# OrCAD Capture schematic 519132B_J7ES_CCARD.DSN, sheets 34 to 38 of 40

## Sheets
34 38.DEBUG: size C; rev: A
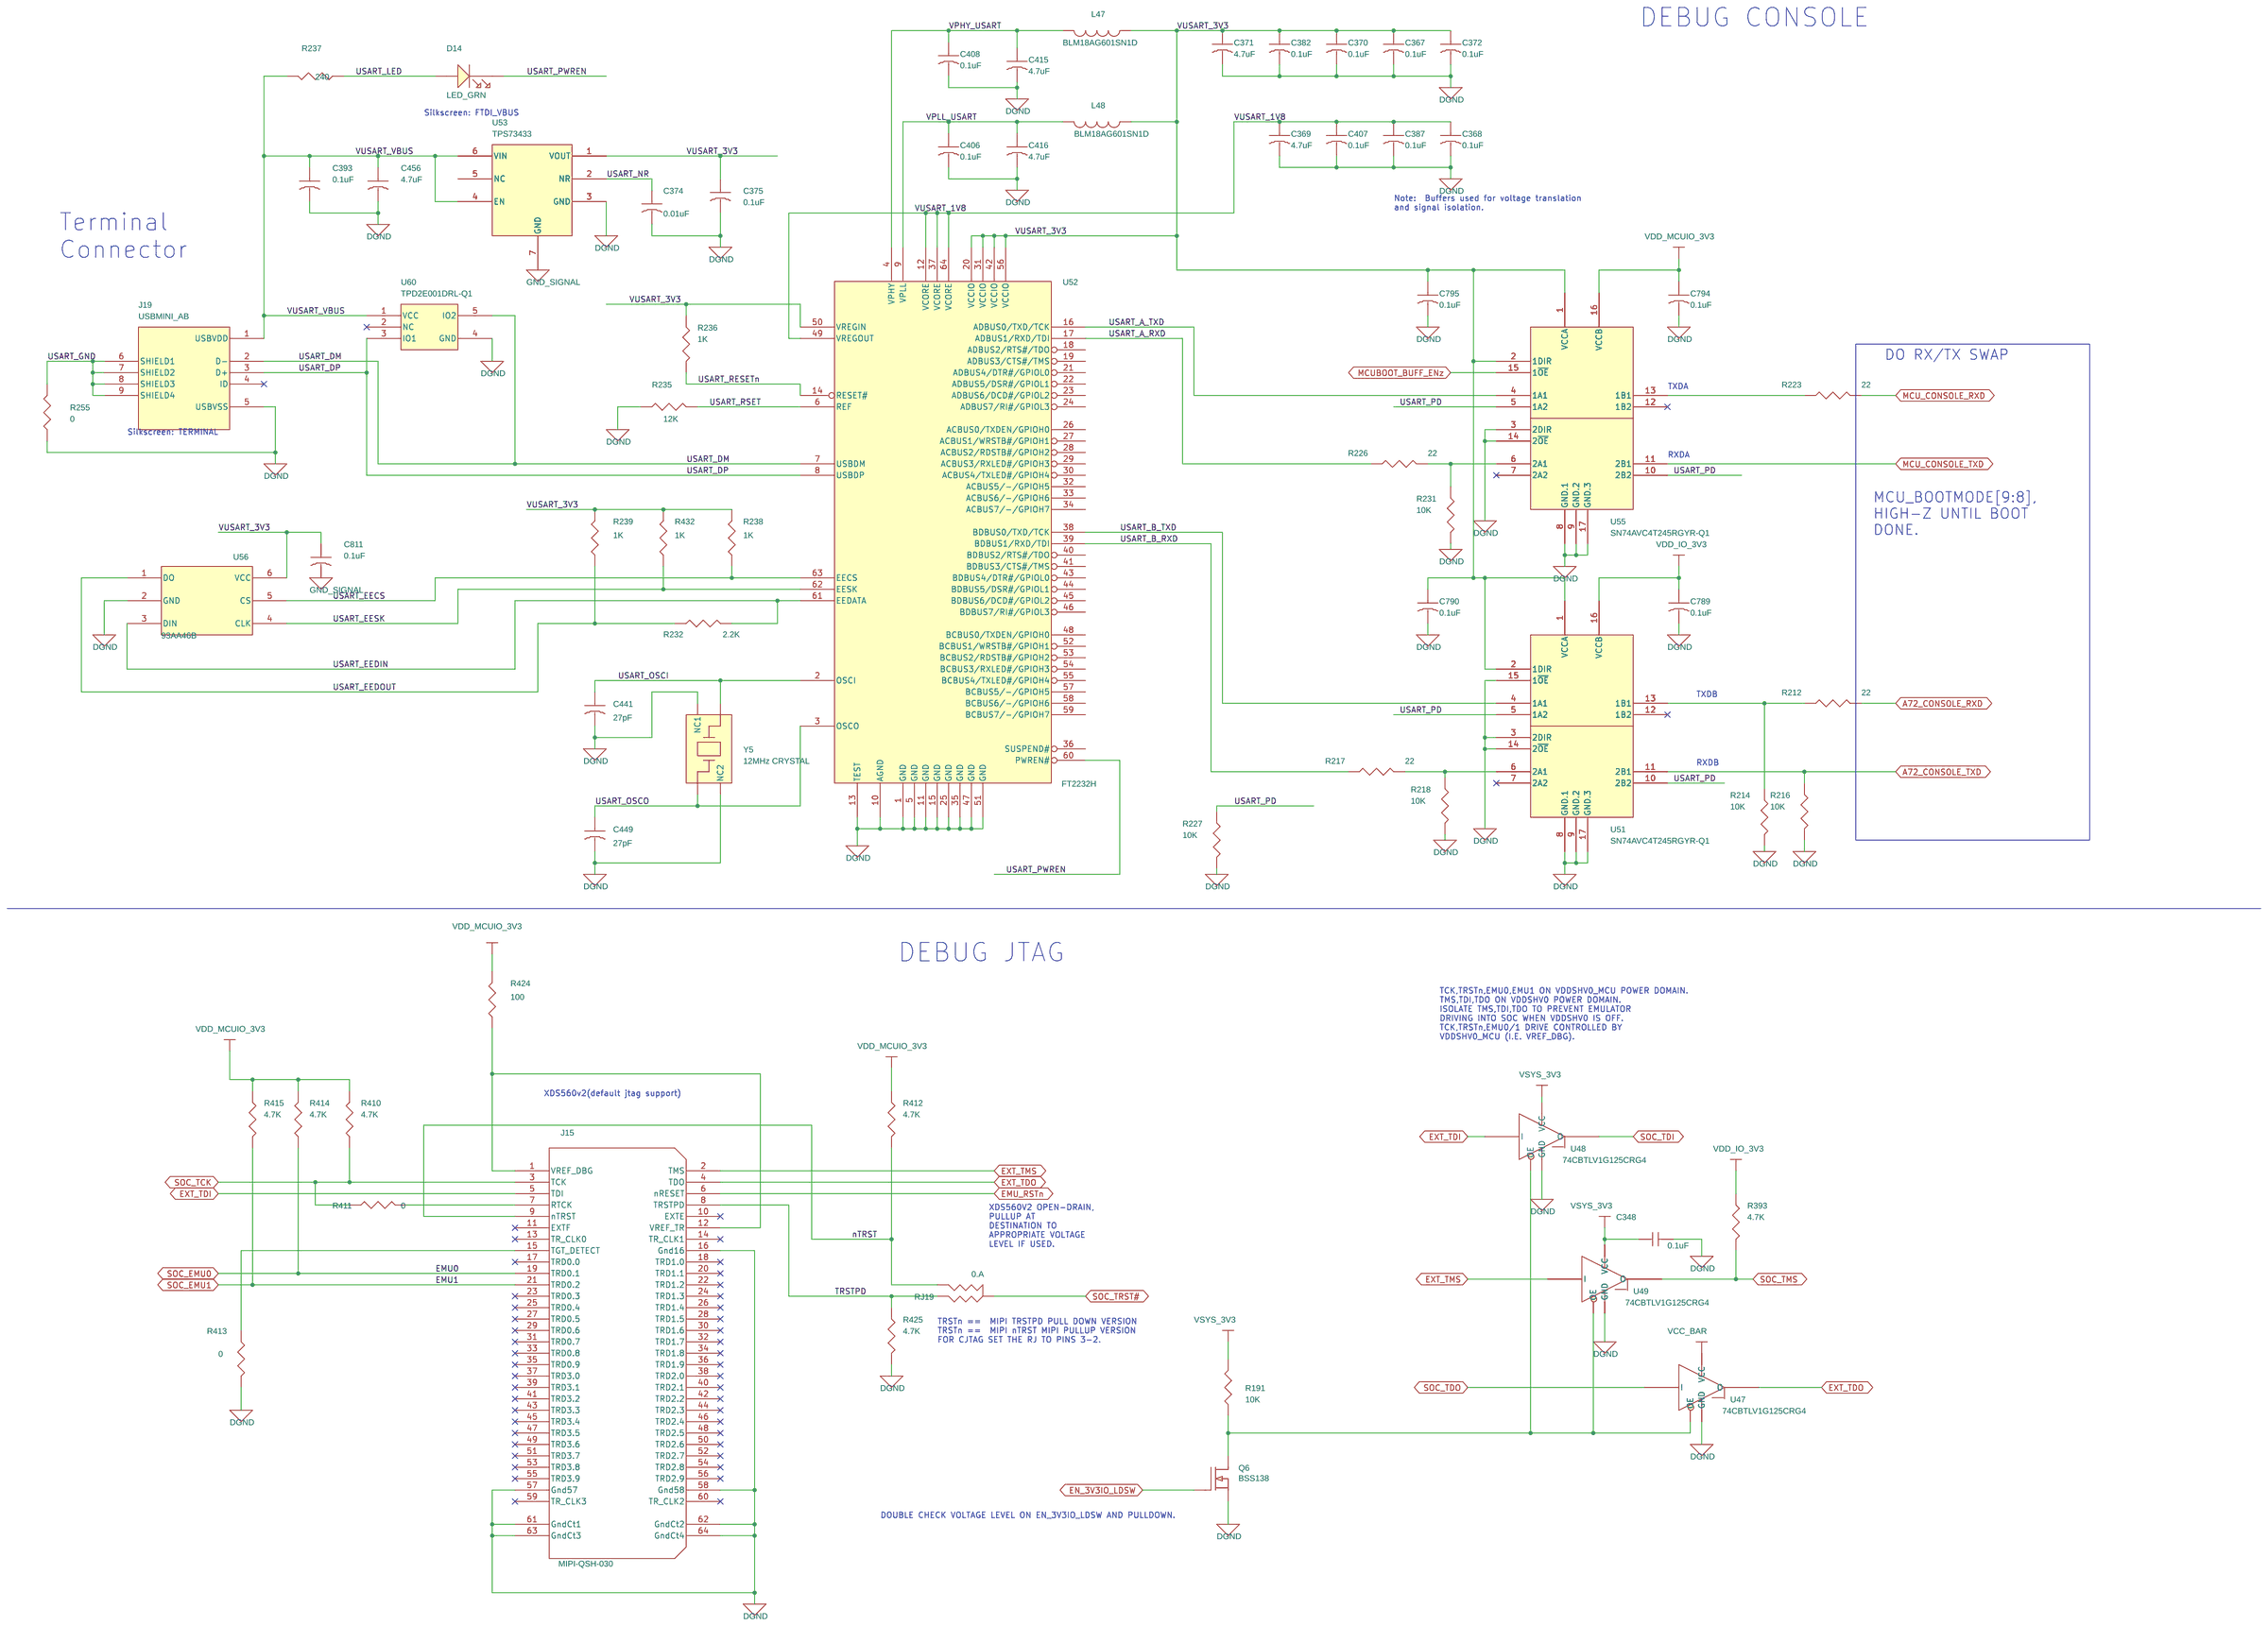
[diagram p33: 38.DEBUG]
35 39.TUNER: size C; rev: A
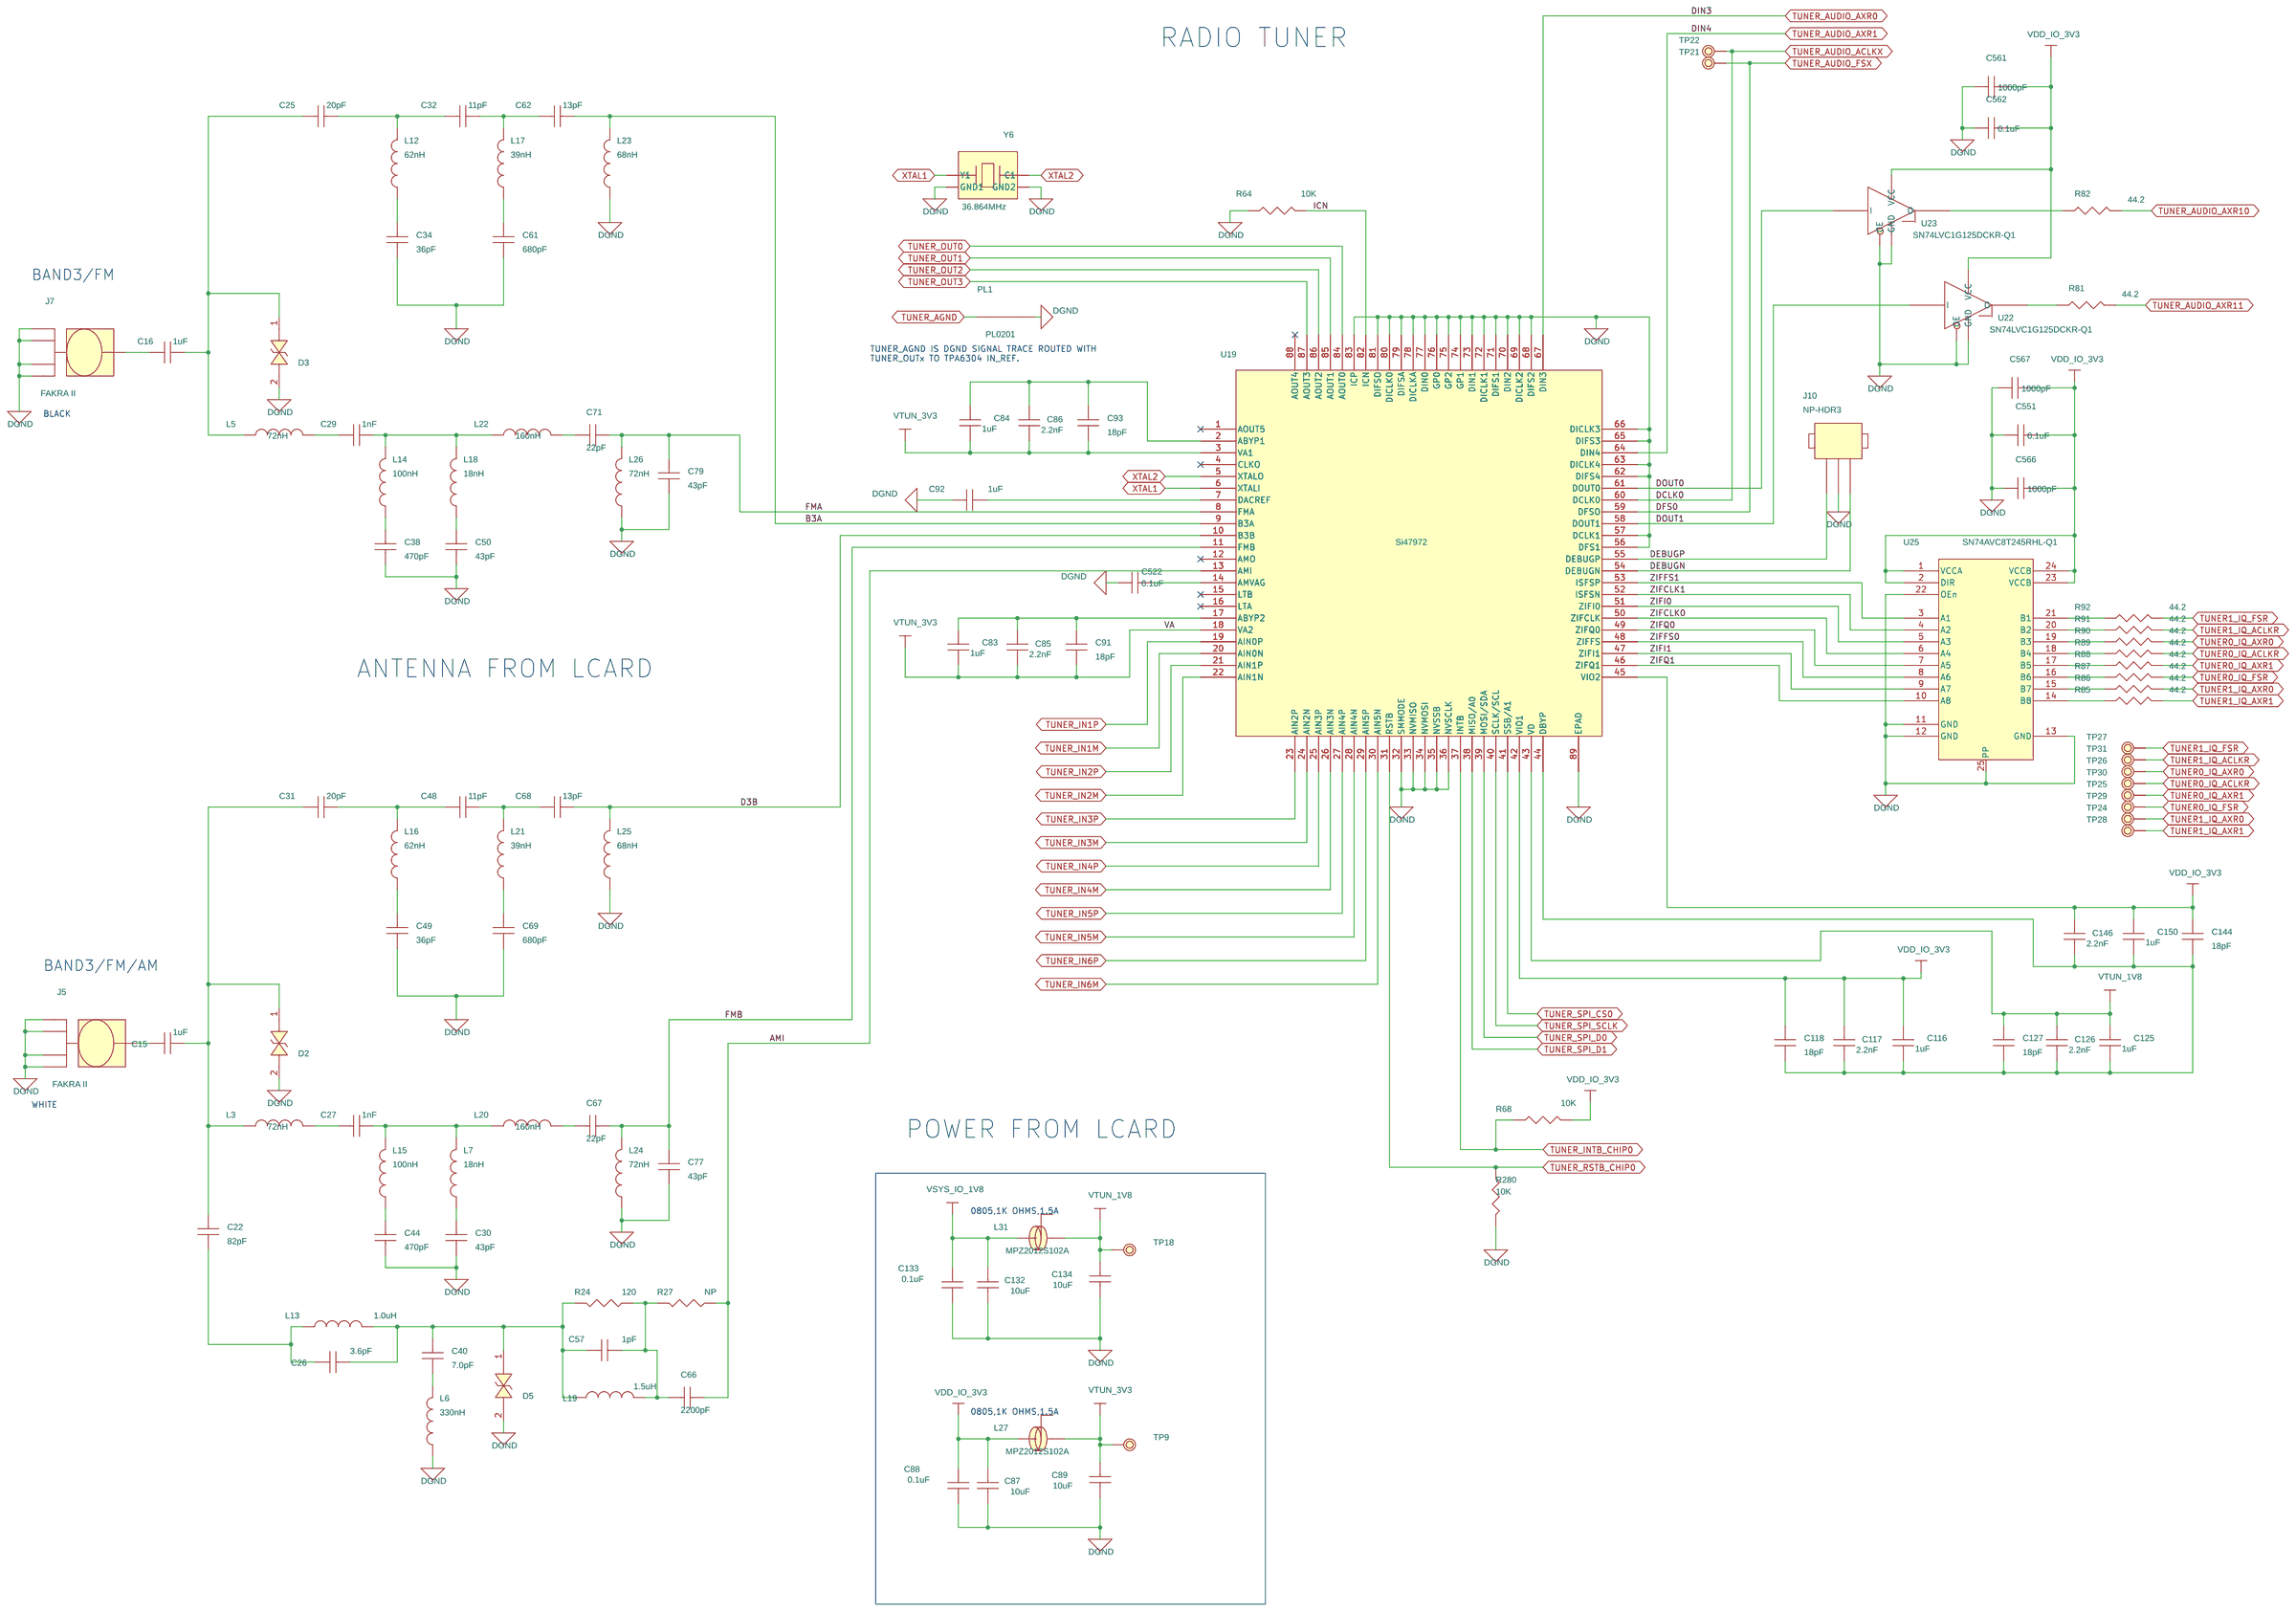
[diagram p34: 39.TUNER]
36 40. DEBUG SDCARD: size C; rev: A
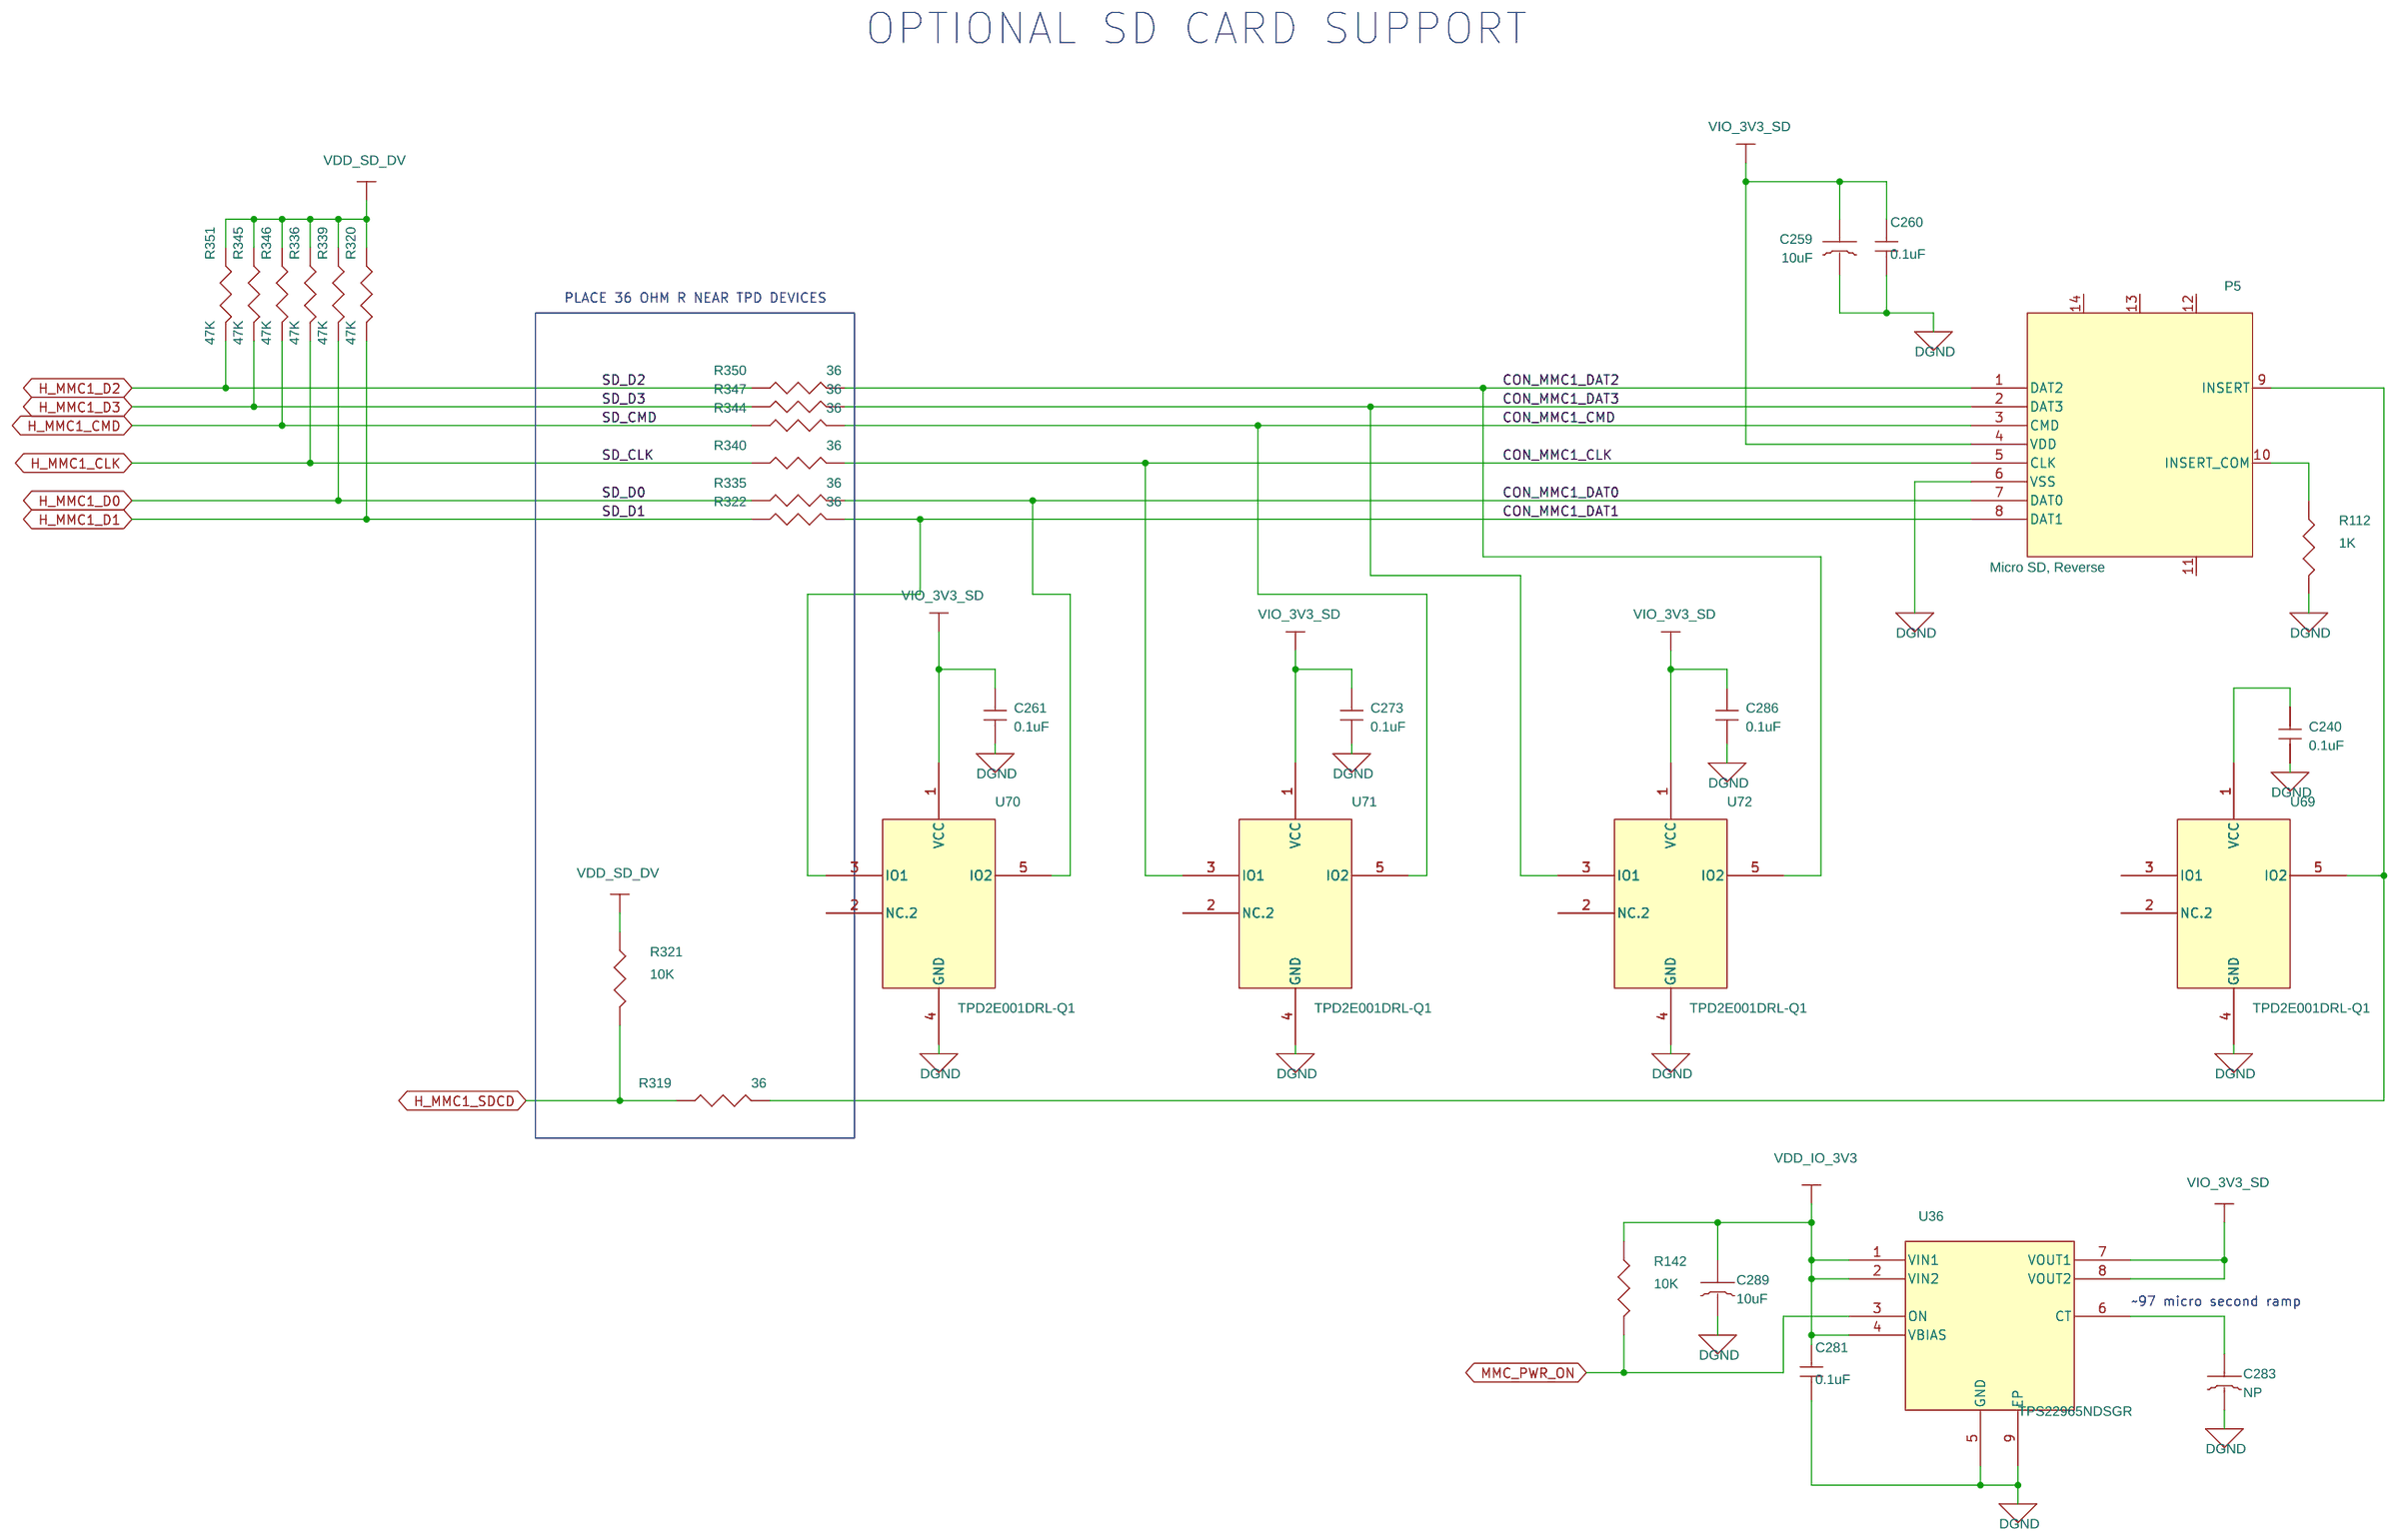
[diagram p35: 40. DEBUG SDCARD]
37 32.ENET/CAN: size C; rev: B
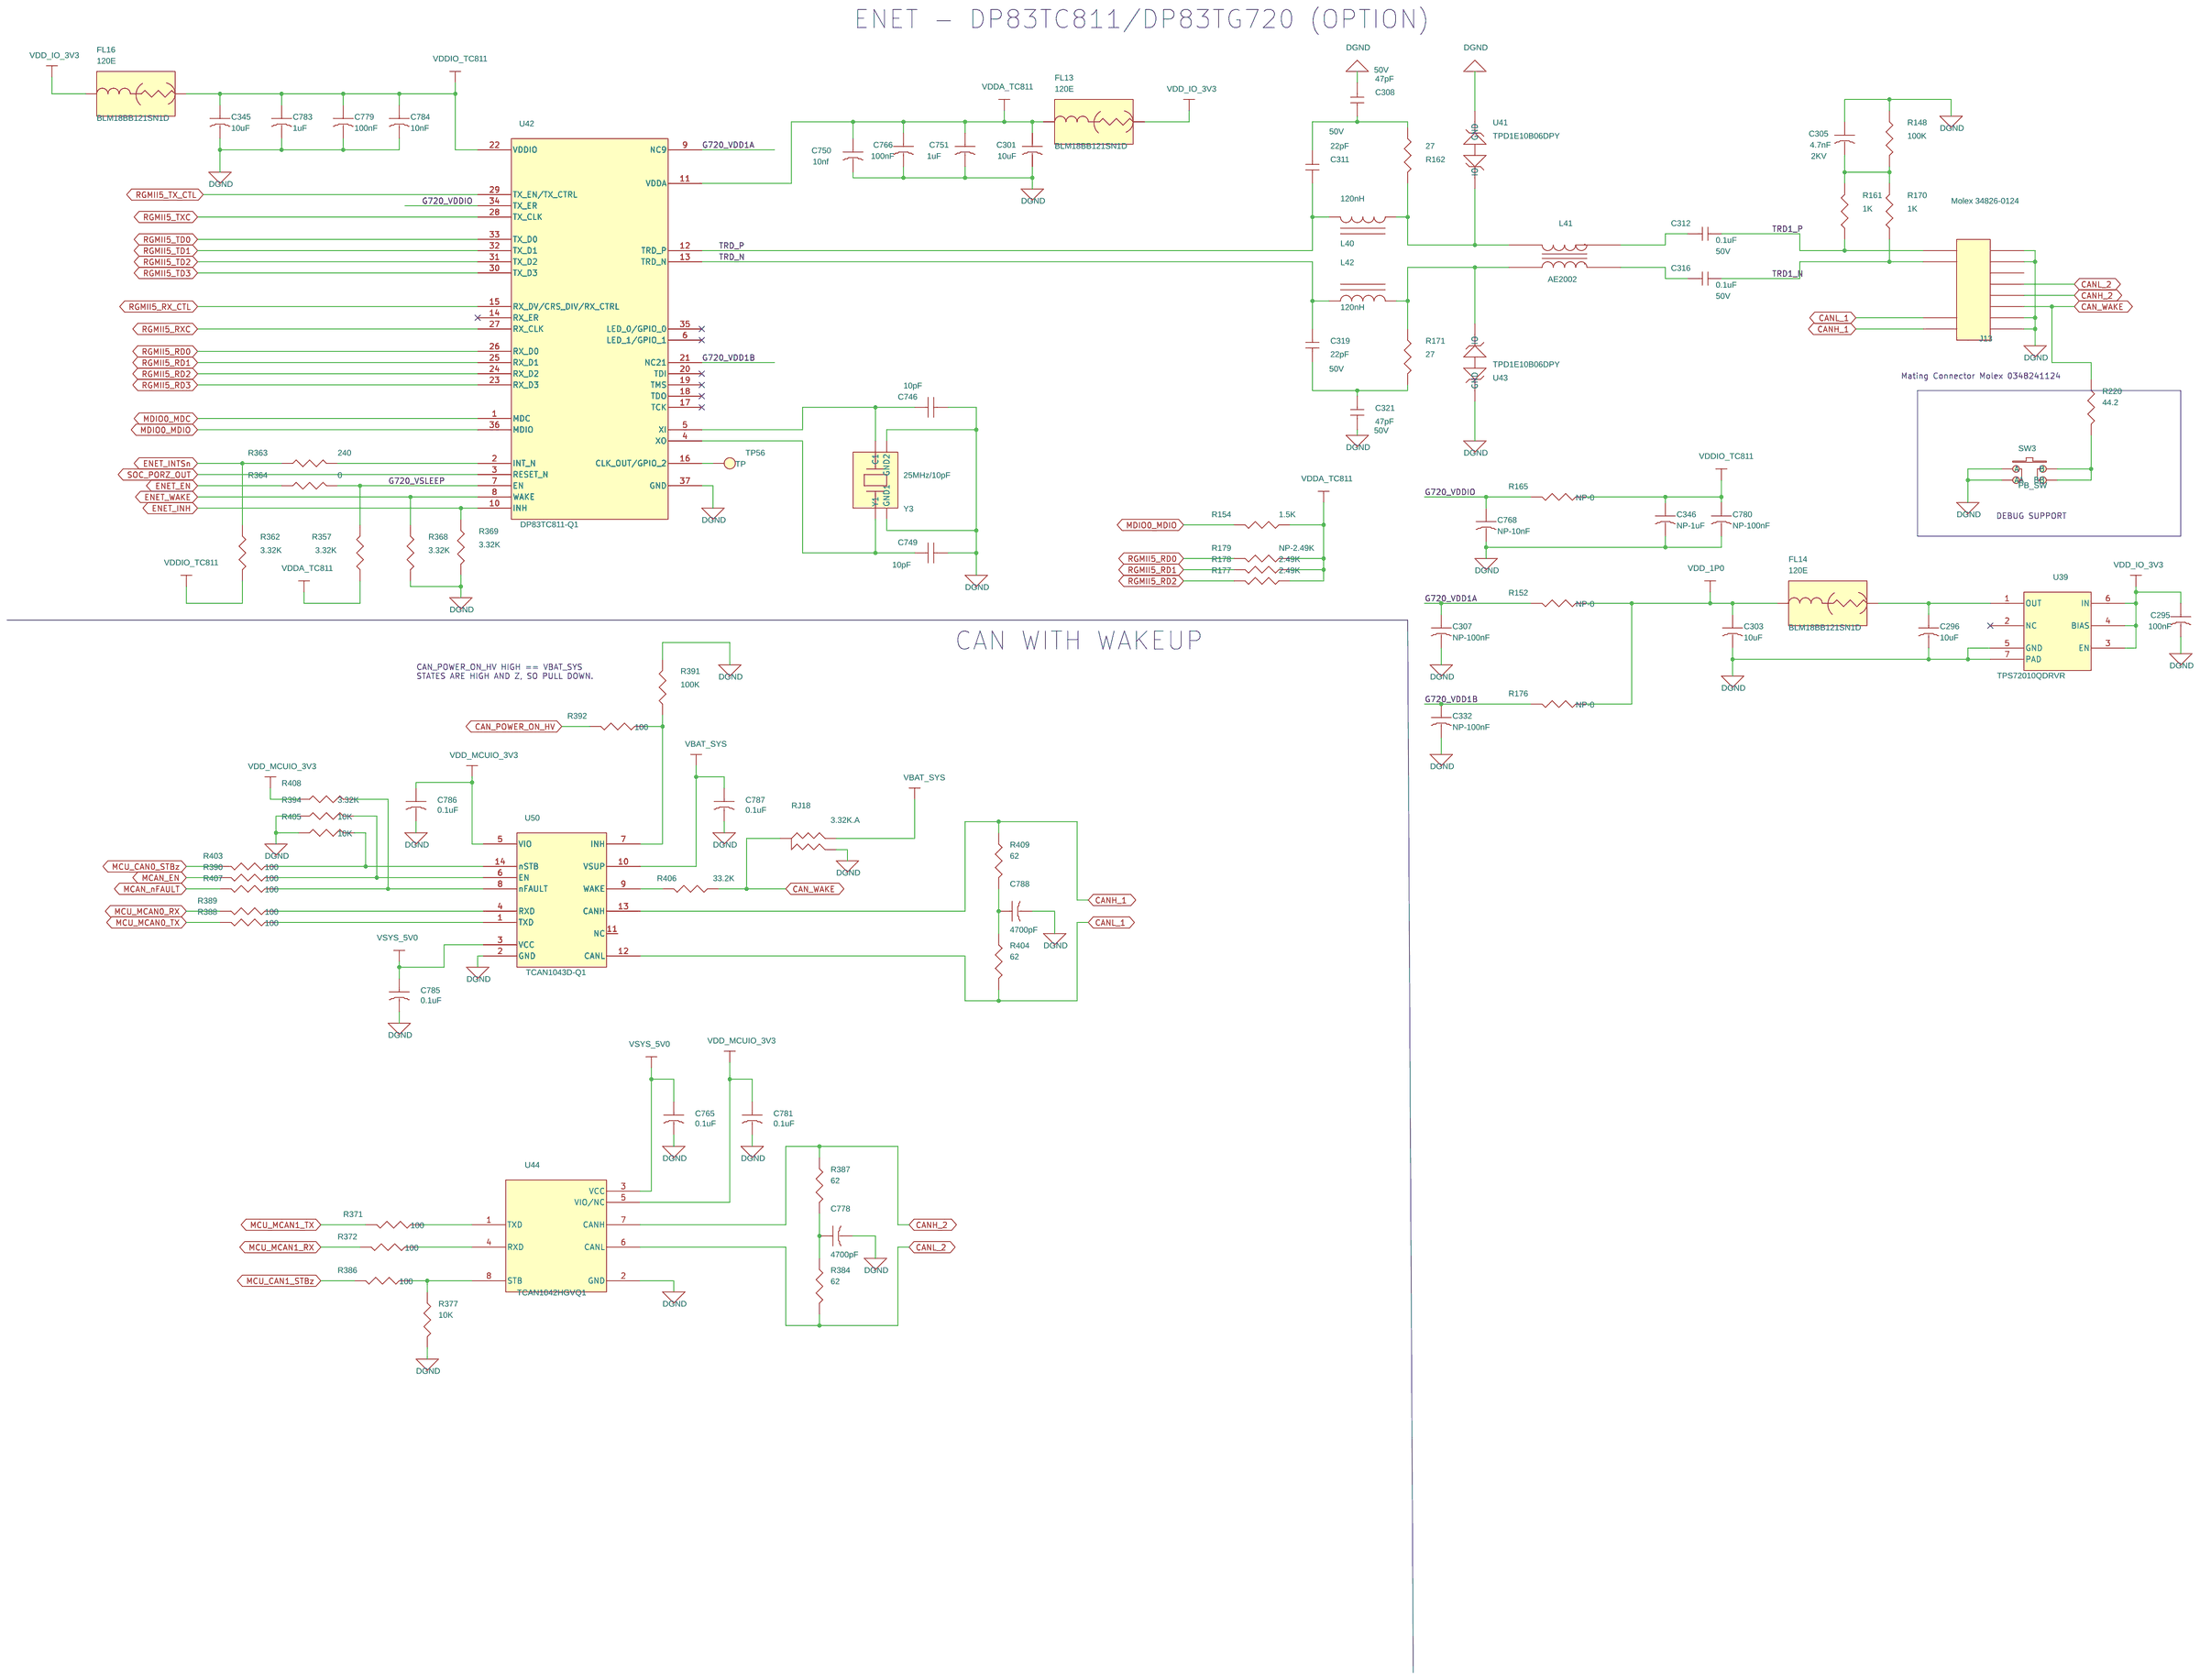
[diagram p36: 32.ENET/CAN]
38 34. USB HUB/WIFI: size C; rev: A
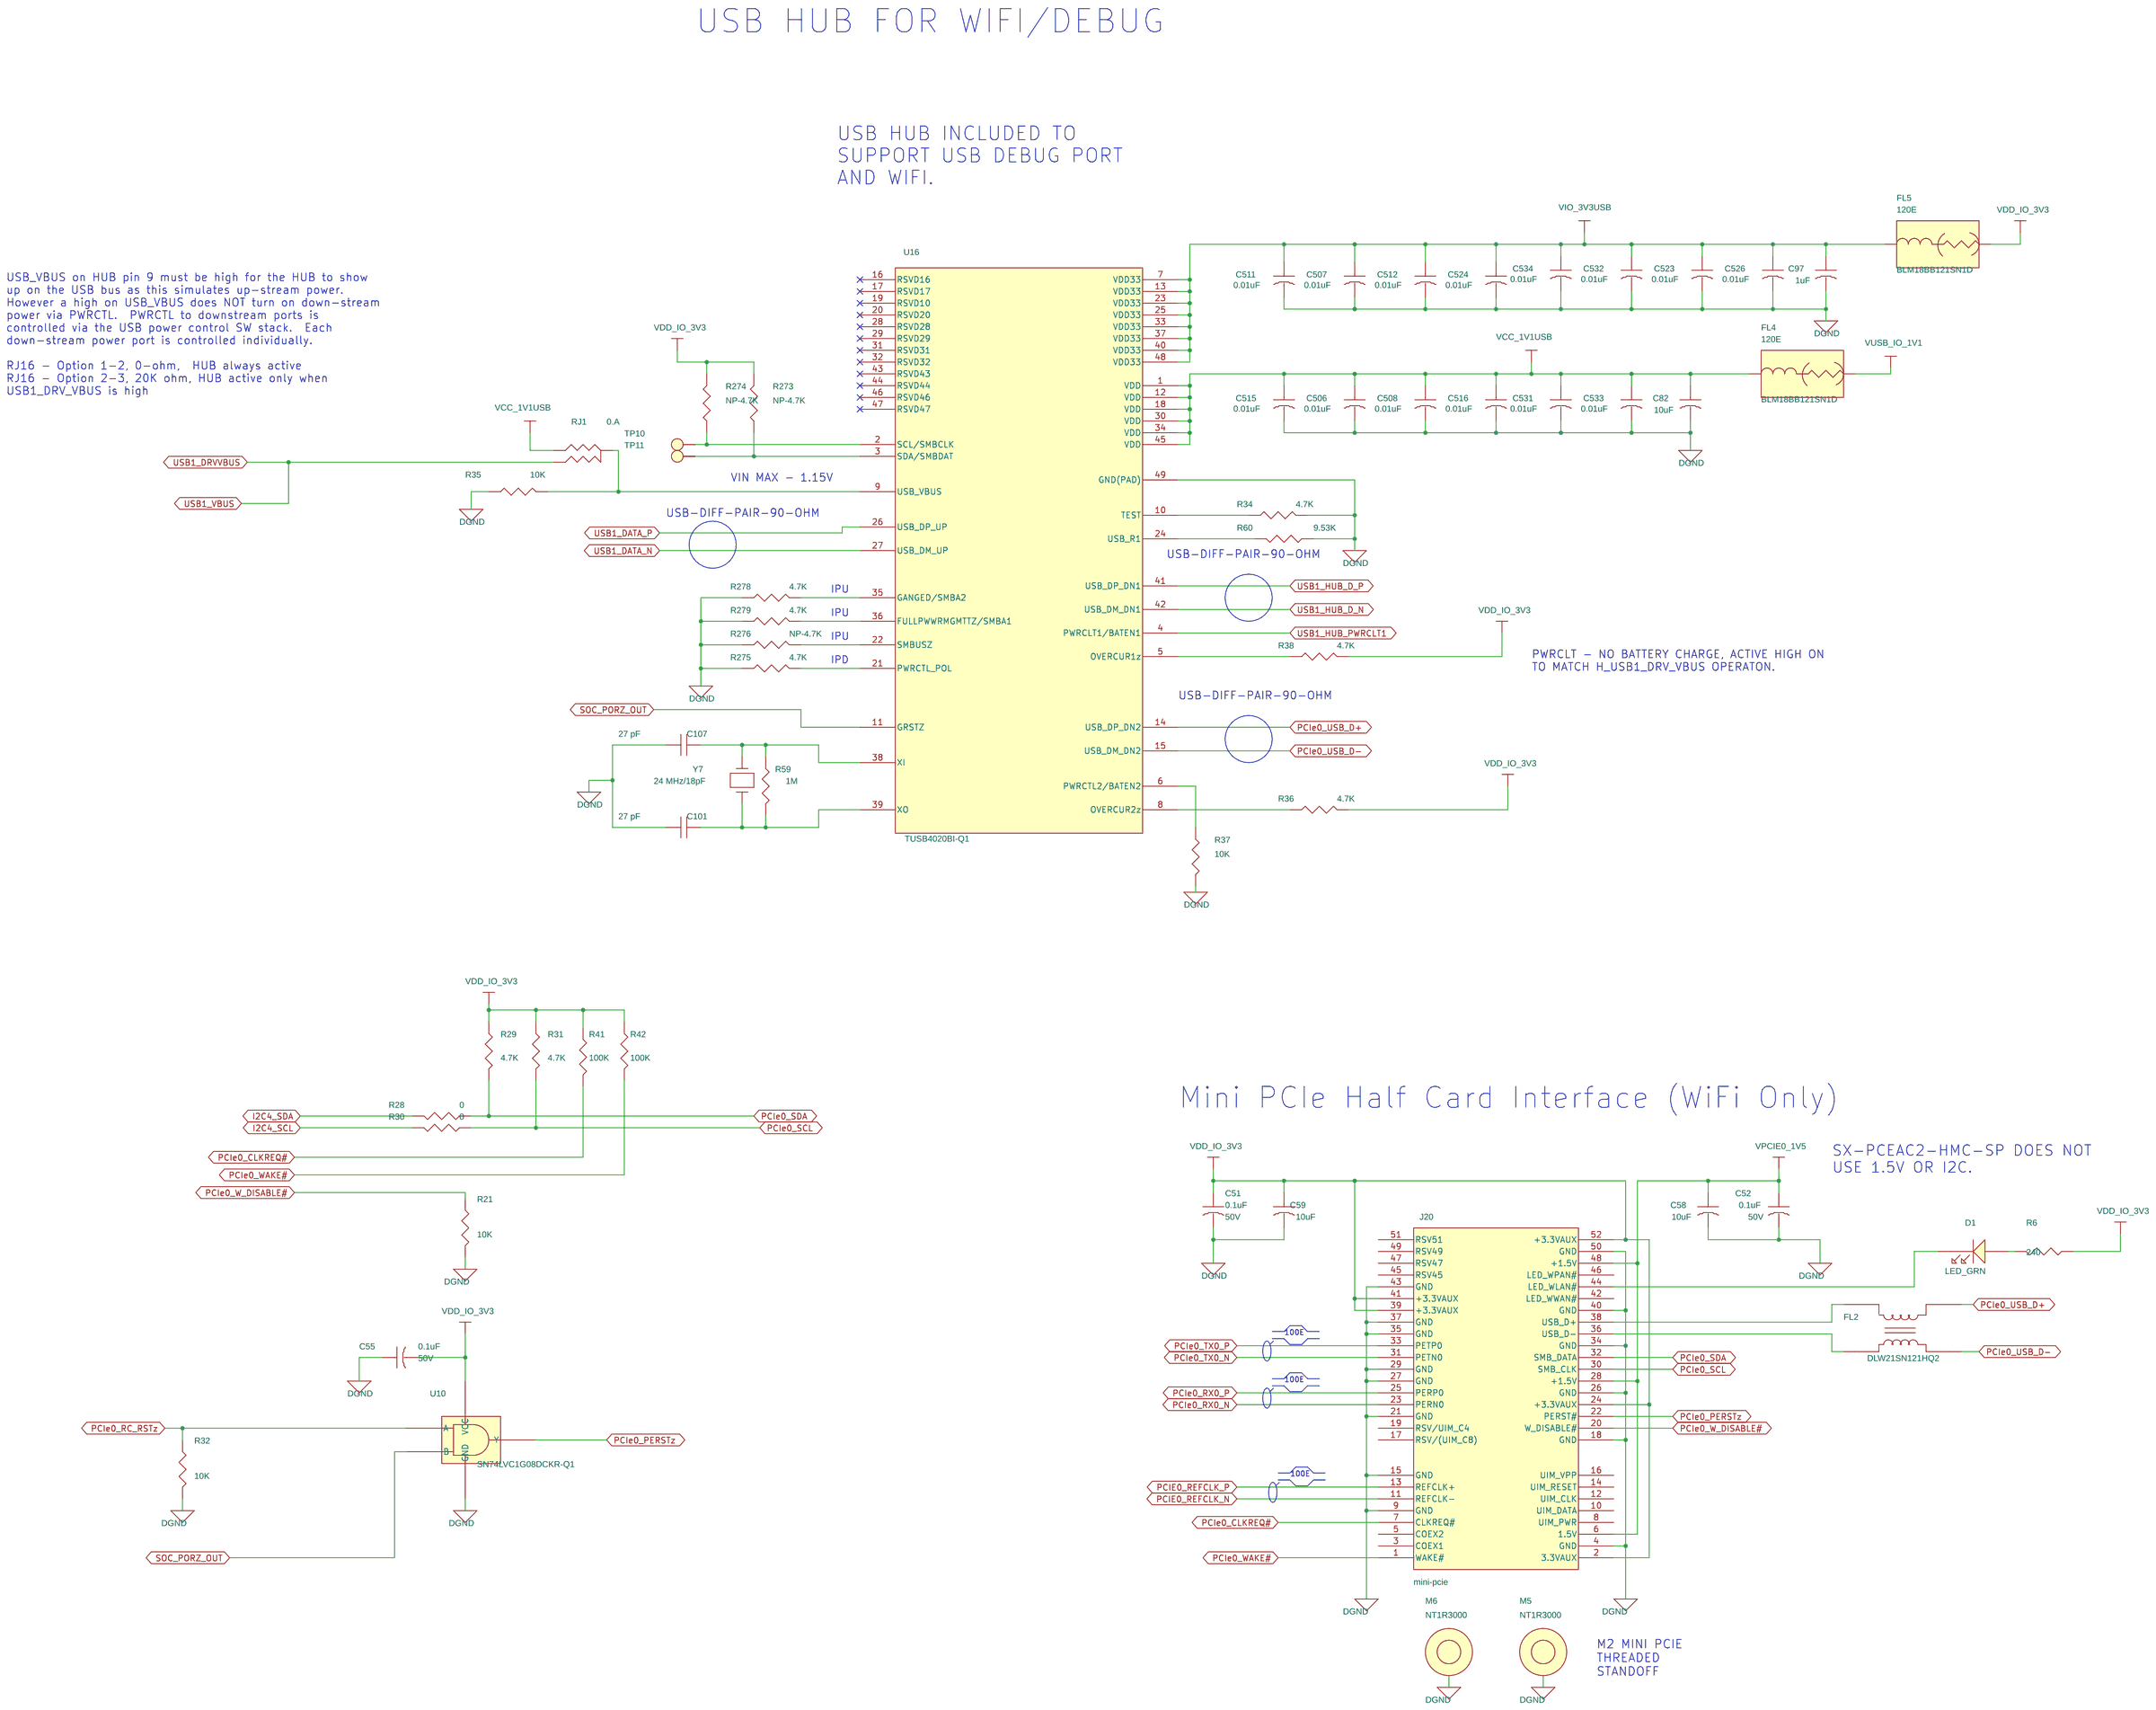
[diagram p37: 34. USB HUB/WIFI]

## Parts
sheet 32.ENET/CAN
C295  100nF  [c402-25]
C296  10uF  [c805-35x60]
C301  10uF  [c805-35x60]
C303  10uF  [c805-35x60]
C305  4.7nF  [c1210-70x102]
C307  NP-100nF  [c402-25]
C308  47pF  [c402-25]
C311  22pF  [c603-35x45]
C312  0.1uF  [c603-35x45]
C316  0.1uF  [c603-35x45]
C319  22pF  [c603-35x45]
C321  47pF  [c402-25]
C332  NP-100nF  [c402-25]
C345  10uF  [c805-35x60]
C346  NP-1uF  [c402-25]
C746  10pF  [c402-25]
C749  10pF  [c402-25]
C750  10nf  [c402-25]
C751  1uF  [c402-25]
C765  0.1uF  [c402-25]
C766  100nF  [c402-25]
C768  NP-10nF  [c402-25]
C778  4700pF  [c402-25]
C779  100nF  [c402-25]
C780  NP-100nF  [c402-25]
C781  0.1uF  [c402-25]
C783  1uF  [c402-25]
C784  10nF  [c402-25]
C785  0.1uF  [c402-25]
C786  0.1uF  [c402-25]
C787  0.1uF  [c402-25]
C788  4700pF  [c402-25rd]
FL13  120E  [EMIFIL_BLM18A_0603]
FL14  120E  [EMIFIL_BLM18A_0603]
FL16  120E  [EMIFIL_BLM18A_0603]
J13  Molex 34826-0124  [molex-34826-0124]
L40  120nH  [ind1608-27x40]
L41  AE2002  [choke4-ae2002]
L42  120nH  [ind1608-27x40]
R148  100K  [r402-25]
R152  NP-0  [r402-25]
R154  1.5K  [r402-25]
R161  1K  [r402-25]
R162  27  [r402-25]
R165  NP-0  [r402-25]
R170  1K  [r402-25]
R171  27  [r402-25]
R176  NP-0  [r402-25]
R177  2.49K  [r402-25]
R178  2.49K  [r402-25]
R179  NP-2.49K  [r402-25]
R220  44.2  [r201-18p5x15]
R357  3.32K  [r402-25]
R362  3.32K  [r402-25]
R363  240  [r402-25]
R364  0  [r402-25]
R368  3.32K  [r402-25]
R369  3.32K  [r402-25]
R371  100  [r402-25]
R372  100  [r402-25]
R377  10K  [r402-25]
R384  62  [r1206-40x70]
R386  100  [r402-25]
R387  62  [r1206-40x70]
R388  100  [r402-25]
R389  100  [r402-25]
R390  100  [r402-25]
R391  100K  [r402-25]
R392  100  [r402-25]
R394  10K  [r402-25]
R403  100  [r402-25]
R404  62  [r1206-40x70]
R405  10K  [r402-25]
R406  33.2K  [r402-25]
R407  100  [r402-25]
R408  3.32K  [r402-25]
R409  62  [r1206-40x70]
RJ18  3.32K.A  [JMP402-25]
SW3  PB_SW  [SW4-7914G]
TP56  TP  [tp-30RD13]
U39  TPS72010QDRVR  [drv6-12x30]
U41  TPD1E10B06DPY  [dpy]
U42  DP83TC811-Q1  [rnd36-24x10]
U43  TPD1E10B06DPY  [dpy]
U44  TCAN1042HGVQ1  [so8-25x75]
U50  TCAN1043D-Q1  [so14-25x75]
Y3  25MHz/10pF  [xtal4-abm11]
sheet 34. USB HUB/WIFI
C51  0.1uF  [c402-25]
C52  0.1uF  [c402-25]
C55  0.1uF  [c402-25]
C58  10uF  [c805-35x60]
C59  10uF  [c805-35x60]
C82  10uF  [c603-35x45]
C97  1uF  [c603-35x45]
C101  27 pF  [C402-25]
C107  27 pF  [C402-25]
C506  0.01uF  [c402-25]
C507  0.01uF  [c402-25]
C508  0.01uF  [c402-25]
C511  0.01uF  [c402-25]
C512  0.01uF  [c402-25]
C515  0.01uF  [c402-25]
C516  0.01uF  [c402-25]
C523  0.01uF  [c402-25]
C524  0.01uF  [c402-25]
C526  0.01uF  [c402-25]
C531  0.01uF  [c402-25]
C532  0.01uF  [c402-25]
C533  0.01uF  [c402-25]
C534  0.01uF  [c402-25]
D1  LED_GRN  [led1206-59x59]
FL2  DLW21SN121HQ2  [EMI-36X15-DLW21]
FL4  120E  [EMIFIL_BLM18A_0603]
FL5  120E  [EMIFIL_BLM18A_0603]
J20  mini-pcie  [molex-67910-0002]
M5  NT1R3000  [mhp098-175pip]
M6  NT1R3000  [mhp098-175pip]
R6  240  [r402-25]
R21  10K  [r402-25]
R28  0  [r402-25]
R29  4.7K  [r402-25]
R30  0  [r402-25]
R31  4.7K  [r402-25]
R32  10K  [r402-25]
R34  4.7K  [r402-25]
R35  10K  [r402-25]
R36  4.7K  [r402-25]
R37  10K  [r402-25]
R38  4.7K  [r402-25]
R41  100K  [r402-25]
R42  100K  [r402-25]
R59  1M  [r402-25]
R60  9.53K  [r402-25]
R273  NP-4.7K  [r402-25]
R274  NP-4.7K  [r402-25]
R275  4.7K  [r402-25]
R276  NP-4.7K  [r402-25]
R278  4.7K  [r402-25]
R279  4.7K  [r402-25]
RJ1  0.A  [JMP402-25]
TP10  TP  [tp-30RD13]
TP11  TP  [tp-30RD13]
U10  SN74LVC1G08DCKR-Q1  [dck-5]
U16  TUSB4020BI-Q1  [php48-12x70]
Y7  24 MHz/18pF  [xtal2-75x94]
sheet 38.DEBUG
C348  0.1uF  [c402-25]
C367  0.1uF  [c402-25]
C368  0.1uF  [c402-25]
C369  4.7uF  [C805-35X60]
C370  0.1uF  [c402-25]
C371  4.7uF  [C805-35X60]
C372  0.1uF  [c402-25]
C374  0.01uF  [c402-25]
C375  0.1uF  [c402-25]
C382  0.1uF  [c402-25]
C387  0.1uF  [c402-25]
C393  0.1uF  [c402-25]
C406  0.1uF  [c402-25]
C407  0.1uF  [c402-25]
C408  0.1uF  [c402-25]
C415  4.7uF  [C805-35X60]
C416  4.7uF  [C805-35X60]
C441  27pF  [c402-25]
C449  27pF  [c402-25]
C456  4.7uF  [C805-35X60]
C789  0.1uF  [c402-25]
C790  0.1uF  [c402-25]
C794  0.1uF  [c402-25]
C795  0.1uF  [c402-25]
C811  0.1uF  [c402-25]
D14  LED_GRN  [led1206-59x59]
J15  MIPI-QSH-030  [qsh-030-01-f]
J19  USBMINI_AB  [SAMTEC-MUSB]
L47  BLM18AG601SN1D  [l603-35x45]
L48  BLM18AG601SN1D  [l603-35x45]
Q6  BSS138  [SOT23-28X44-GSD]
R191  10K  [r201-18p5x15]
R212  22  [r402-25]
R214  10K  [r402-25]
R216  10K  [r402-25]
R217  22  [r402-25]
R218  10K  [r402-25]
R223  22  [r402-25]
R226  22  [r402-25]
R227  10K  [r402-25]
R231  10K  [r402-25]
R232  2.2K  [r402-25]
R235  12K  [r402-25]
R236  1K  [r402-25]
R237  240  [r402-25]
R238  1K  [r402-25]
R239  1K  [r402-25]
R255  0  [r402-25]
R393  4.7K  [r402-25]
R410  4.7K  [r402-25]
R411  0  [r402-25]
R412  4.7K  [r402-25]
R413  0  [r402-25]
R414  4.7K  [r402-25]
R415  4.7K  [r402-25]
R424  100  [r402-25]
R425  4.7K  [r402-25]
R432  1K  [r402-25]
RJ19  0.A  [JMP402-25]
U47  74CBTLV1G125CRG4  [dck-5]
U48  74CBTLV1G125CRG4  [dck-5]
U49  74CBTLV1G125CRG4  [dck-5]
U51  SN74AVC4T245RGYR-Q1  [rgy16-12x34]
U52  FT2232H  [PQFP64PM]
U53  TPS73433  [drv6-12x30]
U55  SN74AVC4T245RGYR-Q1  [rgy16-12x34]
U56  93AA46B  [DBV6-27X39-6]
U60  TPD2E001DRL-Q1  [drl5-12x40]
Y5  12MHz CRYSTAL  [xtal4-63x50-ecx53b]
sheet 39.TUNER
C15  1uF  [c402-25]
C16  1uF  [c402-25]
C22  82pF  [c402-25]
C25  20pF  [c603-35x45]
C26  3.6pF  [c402-25]
C27  1nF  [c402-25]
C29  1nF  [c402-25]
C30  43pF  [c402-25]
C31  20pF  [c603-35x45]
C32  11pF  [c402-25]
C34  36pF  [c402-25]
C38  470pF  [c402-25]
C40  7.0pF  [c402-25]
C44  470pF  [c402-25]
C48  11pF  [c402-25]
C49  36pF  [c402-25]
C50  43pF  [c402-25]
C57  1pF  [c402-25]
C61  680pF  [c402-25]
C62  13pF  [c402-25]
C66  2200pF  [c402-25]
C67  22pF  [c402-25]
C68  13pF  [c402-25]
C69  680pF  [c402-25]
C71  22pF  [c402-25]
C77  43pF  [c402-25]
C79  43pF  [c402-25]
C83  1uF  [c402-25]
C84  1uF  [c402-25]
C85  2.2nF  [c402-25]
C86  2.2nF  [c402-25]
C87  10uF  [c805-35x60]
C88  0.1uF  [c402-25rd]
C89  10uF  [c805-35x60]
C91  18pF  [c402-25]
C92  1uF  [c402-25]
C93  18pF  [c402-25]
C116  1uF  [c402-25]
C117  2.2nF  [c402-25]
C118  18pF  [c402-25]
C125  1uF  [c402-25]
C126  2.2nF  [c402-25]
C127  18pF  [c402-25]
C132  10uF  [c805-35x60]
C133  0.1uF  [c402-25rd]
C134  10uF  [c805-35x60]
C144  18pF  [c402-25]
C146  2.2nF  [c402-25]
C150  1uF  [c402-25]
C522  0.1uF  [c402-25]
C551  0.1uF  [c402-25]
C561  1000pF  [c402-25]
C562  0.1uF  [c402-25]
C566  1000pF  [c402-25]
C567  1000pF  [c402-25]
D2  ESD DIODE  [esd402]
D3  ESD DIODE  [esd402]
D5  ESD DIODE  [esd402]
J5  FAKRA II  [conn-st-fakra]
J7  FAKRA II  [conn-st-fakra]
J10  NP-HDR3  [hph1-3-4025]
L3  72nH  [ind603-aisc-25x40]
L5  72nH  [ind603-aisc-25x40]
L6  330nH  [ind603-aisc-25x40]
L7  18nH  [ind603-aisc-25x40]
L12  62nH  [ind603-aisc-25x40]
L13  1.0uH  [ind0805-40x70]
L14  100nH  [ind603-aisc-25x40]
L15  100nH  [ind603-aisc-25x40]
L16  62nH  [ind603-aisc-25x40]
L17  39nH  [ind603-aisc-25x40]
L18  18nH  [ind603-aisc-25x40]
L19  1.5uH  [ind0805-40x70]
L20  160nH  [ind603-aisc-25x40]
L21  39nH  [ind603-aisc-25x40]
L22  160nH  [ind603-aisc-25x40]
L23  68nH  [ind603-aisc-25x40]
L24  72nH  [ind603-aisc-25x40]
L25  68nH  [ind603-aisc-25x40]
L26  72nH  [ind603-aisc-25x40]
L27  MPZ2012S102A  [l805-35x60]
L31  MPZ2012S102A  [l805-35x60]
PL1  PL0201  [R201PL]
R24  120  [r402-25]
R27  NP  [r402-25]
R64  10K  [r402-25]
R68  10K  [r402-25]
R81  44.2  [r201-18p5x15]
R82  44.2  [r201-18p5x15]
R85  44.2  [r201-18p5x15]
R86  44.2  [r201-18p5x15]
R87  44.2  [r201-18p5x15]
R88  44.2  [r201-18p5x15]
R89  44.2  [r201-18p5x15]
R90  44.2  [r201-18p5x15]
R91  44.2  [r201-18p5x15]
R92  44.2  [r201-18p5x15]
R280  10K  [r402-25]
TP9  TP  [tp-30RD13]
TP18  TP  [tp-30RD13]
TP21  TP  [tp-20RD10]
TP22  TP  [tp-20RD10]
TP24  TP  [tp-20RD10]
TP25  TP  [tp-20RD10]
TP26  TP  [tp-20RD10]
TP27  TP  [tp-20RD10]
TP28  TP  [tp-20RD10]
TP29  TP  [tp-20RD10]
TP30  TP  [tp-20RD10]
TP31  TP  [tp-20RD10]
U19  Si47972  [qfn88-12x12]
U22  SN74LVC1G125DCKR-Q1  [dck-5]
U23  SN74LVC1G125DCKR-Q1  [dck-5]
U25  SN74AVC8T245RHL-Q1  [rhl24-pvqfn-ti]
Y6  36.864MHz  [xtal4-55x47-3225]
sheet 40. DEBUG SDCARD
C240  0.1uF  [c201-6p6spc]
C259  10uF  [c603-35x45]
C260  0.1uF  [c201-6p6spc]
C261  0.1uF  [c201-6p6spc]
C273  0.1uF  [c201-6p6spc]
C281  0.1uF  [c201-6p6spc]
C283  NP  [c603-35x45]
C286  0.1uF  [c201-6p6spc]
C289  10uF  [c603-35x45]
P5  Micro SD, Reverse  [molex-502774-0891]
R112  1K  [r201-6p6spc]
R142  10K  [r402-25]
R319  36  [r201-18p5x15]
R320  47K  [r201-6p6spc]
R321  10K  [r402-25]
R322  36  [r201-18p5x15]
R335  36  [r201-18p5x15]
R336  47K  [r201-6p6spc]
R339  47K  [r201-6p6spc]
R340  36  [r201-18p5x15]
R344  36  [r201-18p5x15]
R345  47K  [r201-6p6spc]
R346  47K  [r201-6p6spc]
R347  36  [r201-18p5x15]
R350  36  [r201-18p5x15]
R351  47K  [r201-6p6spc]
U36  TPS22965NDSGR  [WSON8_19-68_80X80_0-8]
U69  TPD2E001DRL-Q1  [drl5-12x40]
U70  TPD2E001DRL-Q1  [drl5-12x40]
U71  TPD2E001DRL-Q1  [drl5-12x40]
U72  TPD2E001DRL-Q1  [drl5-12x40]

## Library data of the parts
C295 C307 C332 C780 = CAP: Part #: C0402-NOPOP; Voltage: 16V
C296 C303 = CAP: Part #: C0805-NOPOP; Voltage: 6.3V
C58 C59 C301 C345 = CAP: Part #: 104936-0101R; Voltage: 6.3V
C305 = CAP: Manufacturer ref: C113; Mfr: Kemet Electronics Corporation; MfrNum: C1210X472KGRACAUTO; Part #: 105350-1472R; Voltage: 2KV
C308 C321 = CAP_NP: Part #: 101782-1474R; Voltage: 50V
C311 C319 = CAP_NP: Part #: 101002-1224R; Voltage: 50V
C312 C316 = CAP_NP: Part #: 103885-1100R; Voltage: 50V
C346 = CAP: Part #: C0402-NOPOP; Voltage: 10V
C746 C749 = CAP_NP_3: Alternate_mfr_part_number_B: 102366-1685R; Part #: 101782-1104R; Voltage: 50V
C374 C750 C784 = CAP: Part #: 104725-1101R; Voltage: 50V
C751 C783 = CAP: Part #: 104911-0100R; Voltage: 10V
C367 C368 C370 C372 C375 C382 C387 C393 C406-C408 C765 C766 C779 C781 C785-C787 C789 C790 C794 C795 C811 = CAP: Part #: 104446-1100R; Voltage: 16V
C768 = CAP: Part #: C0402-NOPOP; Voltage: 50V
C778 C788 = CAP: Part #: 103217-1472R; Voltage: 25V
FL4 FL5 FL13 FL14 FL16 = EMIFILTER_IND: PASSIVE FILTER EMI 120E 0603; Chkd/date: MAZHAR/030809; Crtd /date: USMAN/070109; Custom_Duty: 24%; Customs_HS_Code: 85437099; Distributor_name: DIGIKEY; Distributor_part_number: 490-1020-1-ND; Height: 0.95MM; Mfr_name: MURATA; Mfr_part_number: BLM18BB121SN1D; Mistral Part No: 130009030758; Package: 0603; Part #: 104392-1201R; Part_type: FILTER; Project: OMAP_EVM; Datasheet: Y:\MIS_DATABASE\DATASHEETS\ICS\MISC\BLM18B.PDF
J13 = Molex34826-0124: Part #: 104788-0012R
L40 L42 = CHOKE_HASH-IRON: Part #: 105291-1120R
L41 = CHOKE_CM_AE2002: Part #: 104953-0001R
R41 R42 R148 R391 = R: Part #: 102145-1004R
R27 R152 R165 R176 R179 = R: Part #: R0402-NOPOP
R154 = R: Part #: 102145-1502R
R161 R170 = R_2: Part #: 102145-1002R
R162 R171 = R: Part #: 101370-2700R
R177 R178 = R: Part #: 102145-2492R
R220 = R: Part #: 103413-4420R
R357 R362 R368 R369 R408 = R: Part #: 102145-3322R
R6 R237 R363 = R: Part #: 102145-2401R
R255 R364 R411 R413 = R: Part #: 101370-0001R
R371 R372 R386 R388-R390 R392 R403 R407 R424 = R: Part #: 102145-1001R
R37 R68 R280 R377 R394 R405 = R: Part #: 102145-1003R
R384 R387 R404 R409 = R: Part #: 100155-6200R
R406 = R: Part #: 102145-3323R
RJ18 = RJUMP3: Part #: 102145-3322R
SW3 = SW_PUSHBUTTON_3: Part #: 101023-0001R
TP10 TP11 TP56 = TESTPOINT: Part #: TP-30RD13-NO-POP
U39 = TPS72010QDRVR: Part #: 105292-0001R
U41 U43 = TPD1E10B09: Part #: 104615-0001R
U42 = DP83TC811-Q1: Part #: 104919-0001R
U44 = SN65HVDA541: Part #: 104828-0001R
U50 = TCAN1043D-Q1: Part #: 105189-0001R
Y3 = CRYSTAL_4-PIN_0: Part #: 104951-2500R
C51 C52 C55 = CAP: CAP CERAMIC 0.1uF 50V 10% X7R 0402; Chkd/date: MANIRAJA/230418; Crtd /date: ALVY/230418; Custom_Duty: 15%; Customs_HS_Code: 85322990; Distributor_name: DIGIKEY; Distributor_part_number: 587-3498-1-ND; Footprint Path: Y:\MIS_DATABASE\Library\ALTIUM_TOOL\PCB_FOOTPRINTS\Altium_Footprint_Lib.PcbLib; Height: 0.55MM; Library Path: Y:\MIS_DATABASE\Library\ALTIUM_TOOL\SCHEMATICS_PARTS\MS_DISCRETE_Library.schlib; Mfr_name: TAIYO YUDEN; Mfr_part_number: UMK105B7104KV-FR; Mistral Part No: 120011100014-R; Package: 0402; Part #: 104910-1100R; Part_type: CAPACITORS\CERAMIC; Project: GC150_PHASE-II_AB; RoHS: RoHS; Temperature: -55°C+125°C; Tolerance: 10%; Voltage: 50V; Wattage: NA; Weight: 0.65mg; Datasheet: Y:\MIS_DATABASE\DATASHEETS\CAPACITORS\UMK105B7104KV-FR.PDF
C82 = CAP: Part #: 105049-0101R; RATING: 6.3V
C97 = CAP: Part #: 104723-0100R; RATING: 16V; Voltage: 16V
C101 C107 = CAP_NP_3: Part #: 105029-1274R
C506-C508 C511 C512 C515 C516 C523 C524 C526 C531-C534 = CAP: Part #: 104725-1101R; RATING: 50V; Voltage: 50V
D1 D14 = LED_RED_0: Part #: 100823-0001R
FL2 = DLW21SN121HQ2: Part #: 104184-1201R
J20 = mini-pcie: Part #: 103906-0001R
M5 M6 = NT1R3000: Part #: 105317-0001R
R21 R32 = RESISTOR: RES 10K 1/16W 5% 0402; Chkd/date: VASANTHA/061216; Crtd /date: MAZHAR/230805; Custom_Duty: 15%; Customs_HS_Code: 85332119; Distributor_name: DIGIKEY; Distributor_part_number: 311-10KJRCT-ND; Footprint Path: Y:\MIS_DATABASE\Library\ALTIUM_TOOL\PCB_FOOTPRINTS\Altium_Footprint_Lib.PcbLib; Height: 0.40MM; Library Path: Y:\MIS_DATABASE\Library\ALTIUM_TOOL\SCHEMATICS_PARTS\MS_DISCRETE_Library.schlib; Mfr_name: YAGEO AMERICA; Mfr_part_number: RC0402JR-0710KL; Mistral Part No: 110011060021-R; Package: 0402; Part #: 102145-1003R; Part_type: RESISTORS\FIXED; Project: HSE; RoHS: RoHS; Temperature: -55°C+155°C; Tolerance: 5%; Voltage: NA; Wattage: 1/16W; Weight: 0.65mg; Datasheet: Y:\MIS_DATABASE\DATASHEETS\RESISTORS\RCXXXXL-SER_MAR18.PDF
R28 R30 = RESISTOR: RES 0E 1/10W JUMPER 0402; Chkd/date: VASANTHA/061216; Crtd /date: NAVEED/201014; Custom_Duty: 15%; Customs_HS_Code: 85332119; Distributor_name: DIGIKEY; Distributor_part_number: P0.0JCT-ND; Footprint Path: Y:\MIS_DATABASE\Library\ALTIUM_TOOL\PCB_FOOTPRINTS\Altium_Footprint_Lib.PcbLib; Height: 0.40MM; IBISSP_MODLES: VALUE REPEATING 2 TIME; Library Path: Y:\MIS_DATABASE\Library\ALTIUM_TOOL\SCHEMATICS_PARTS\MS_DISCRETE_Library.schlib; Mfr_name: PANASONIC-ECG; Mfr_part_number: ERJ-2GE0R00X; Mistral Part No: 110018030052-R; Package: 0402; Part #: 101370-0001R; Part_type: RESISTORS\FIXED; Project: AEGIS POM; RoHS: RoHS; Temperature: -55°C+155°C; Tolerance: NA; Voltage: NA; Wattage: 1/10W; Weight: 0.8mg; Datasheet: Y:\MIS_DATABASE\DATASHEETS\RESISTORS\PAN-ERJSER_NOV17.PDF
R29 R31 = RESISTOR: RES 4.7K 1/16W 5% 0402; Chkd/date: VASANTHA/130516; Crtd /date: VASANTHA/130516; Custom_Duty: 15%; Customs_HS_Code: 85332119; Distributor_name: DIGIKEY; Distributor_part_number: 311-4.7KJRCT-ND; Footprint Path: Y:\MIS_DATABASE\Library\ALTIUM_TOOL\PCB_FOOTPRINTS\Altium_Footprint_Lib.PcbLib; Height: 0.40MM; Library Path: Y:\MIS_DATABASE\Library\ALTIUM_TOOL\SCHEMATICS_PARTS\MS_DISCRETE_Library.schlib; Mfr_name: YAGEO AMERICA; Mfr_part_number: RC0402JR-074K7L; Mistral Part No: 110011060001-R; Package: 0402; Part #: 102145-4702R; Part_type: RESISTORS\FIXED; Project: TMDXCSK368; RoHS: RoHS; Temperature: -55°C+155°C; Tolerance: 5%; Voltage: NA; Wattage: 1/16W; Weight: 0.65mg; Datasheet: Y:\MIS_DATABASE\DATASHEETS\RESISTORS\RCXXXXL-SER_MAR18.PDF
R34 R36 R38 R275 R278 R279 = R_2: Part #: 102145-4702R
R35 R64 R142 R321 = RESISTOR: Part #: 102145-1003R
R59 = R: Part #: 102145-1005R
R60 = RESISTOR: Part #: 102145-9532R
R273 R274 R276 = R_2: Part #: R0402-NOPOP
RJ1 RJ19 = RJUMP3: Part #: 101370-0001R
U10 = SN74LVC1G08DBVRE4_SOT23-5: IC SINGLE 2-INPUT POSITIVE AND GATE SOT23-5; Chkd/date: SUHAS/221010; Crtd /date: USMAN/151008; Custom_Duty: 15%; Customs_HS_Code: 85423100; Distributor_name: DIGIKEY; Distributor_part_number: SN74LVC1G08DBVRE4-ND; Height: 1.45MM; Mfr_name: TEXAS INSTRUMENTS; Mfr_part_number: SN74LVC1G08DCKR; Mistral Part No: 141009060026-R; Package: DCK5; Part #: 101057-0008R; Part_type: ICS\DIGITAL\GATES; Project: KHAN_MAIN; RoHS: Sb/ Br FREE; Temperature: -40°C+85°C; Datasheet: Y:\MIS_DATABASE\DATASHEETS\ICS\DIGITAL\GATES\SN74LVC1G08.PDF
U16 = TUSB4020BI-Q1: Part #: 105101-0001R
Y7 = CRYSTAL_0: Part #: 101590-0240R
C348 = CAP_NP: Part #: 104446-1100R; RATING: 16V; Voltage: 16V
C369 C371 C415 C416 C456 = CAP: Part #: 101063-0470R; Voltage: 10V
C441 C449 = CAP: Part #: 101782-1274R; Voltage: 50V
J15 = MIPI-QTH-030_1: Part #: 101884-0030R
J19 = USBMINI_B_0: Part #: 101956-0001R
L47 L48 = INDUCTOR: Part #: 101858-6001R
Q6 = MOSFET_N_1: Part #: 100680-0001R
R191 = R: Part #: 103158-1003R
R212 R217 R223 R226 = R: Part #: 101370-2200R
R214 R216 R218 R227 R231 = R_0: Part #: 102145-1003R
R232 = R: Part #: 102145-2202R
R235 = R: Part #: 102145-1203R
R236 R238 R239 R432 = R: Part #: 102145-1002R
R393 R410 R412 R414 R415 R425 = R: Part #: 102145-4702R
U47-U49 = SN74LVC1G125_0: Part #: 101689-0125R
U51 U55 = SN74AVC4T245RGYR_0: Part #: 102649-0245R
U52 = FT2232H_0: Part #: 103172-0001R
U53 = TPS73433_1: Part #: 103554-0001R
U56 = 93C46_3V3: Part #: 103564-0001R
U60 = TPD2E001_0: Part #: 102728-0001R
Y5 = CRYSTAL_9: Part #: 103560-0012R
C15 C16 = CAP_NP_3: Alternate_mfr_part_number_B: 102366-1685R; Part #: 104911-0100R; Voltage: 10V
C22 = CAP_NP_3: Alternate_mfr_part_number_B: 102366-1685R; Part #: 101782-1824R
C25 C31 = CAP_NP_3: Alternate_mfr_part_number_B: 102366-1685R; Part #: 104944-1204R
C26 = CAP_NP_3: Alternate_mfr_part_number_B: 102366-1685R; Part #: 103954-1365R; Voltage: 50V
C27 C29 = CAP_NP_3: Alternate_mfr_part_number_B: 102366-1685R; Part #: 102756-1102R; Voltage: 50V
C30 C50 C77 C79 = CAP_NP_3: Alternate_mfr_part_number_B: 102366-1685R; Part #: 104945-1434R
C32 C48 = CAP_NP_3: Alternate_mfr_part_number_B: 102366-1685R; Part #: 104108-1114R; Voltage: 50V
C34 C49 = CAP_NP_3: Alternate_mfr_part_number_B: 102366-1685R; Part #: 102756-1364R; Voltage: 50V
C38 C44 = CAP_NP_3: Alternate_mfr_part_number_B: 102366-1685R; Part #: 104945-1473R
C40 = CAP_NP_3: Alternate_mfr_part_number_B: 102366-1685R; Part #: 104942-1705R
C57 = CAP_NP_3: Alternate_mfr_part_number_B: 102366-1685R; Part #: 104943-1125R
C61 C69 = CAP_NP_3: Alternate_mfr_part_number_B: 102366-1685R; Part #: 104945-1683R
C62 C68 = CAP_NP_3: Alternate_mfr_part_number_B: 102366-1685R; Part #: 104945-1134R
C66 = CAP_NP_3: Alternate_mfr_part_number_B: 102366-1685R; Part #: 102058-1222R; Voltage: 50V
C67 C71 = CAP_NP_3: Alternate_mfr_part_number_B: 102366-1685R; Part #: 104108-1224R; Voltage: 50V
C83 C84 C92 C116 C125 C150 = CAP_AM_0603_1.0uf_x7r_16v_10_X: Part #: 104911-0100R; Voltage: 10V
C85 C86 C117 C126 C146 = CAP_AM_0603_2.2uf_x7r_6.3v_10_X: Part #: 102058-1222R; Voltage: 50V
C87 C89 C132 C134 = CAP_AM_0805_10uf_x7r_10v_10_X: Part #: 104720-0101R
C88 C133 = CAP_0402_0.1uf_x7r_16v_10%_X_SD: Part #: 104446-1100R
C91 C93 C118 C127 C144 = CAP_NP_3: Alternate_mfr_part_number_B: 102366-1685R; Part #: 102756-1184R; Voltage: 50V
C522 C551 C562 = CAP_AM_0402_0.1uf_x7r_16v_10%_X: Part #: 104446-1100R
C561 C566 C567 = CAP_AM_0402_0.1uf_x7r_16v_10%_X: Part #: 102058-1102R; Voltage: 50V
D2 D3 D5 = DIODE_BI-DIR_TRIG_0: Part #: 104946-0001R
J5 = 59S20X-400L5-Z: Part #: 104894-0002R
J7 = 59S20X-400L5-Z: Part #: 104894-0001R
J10 = HEADER_3: Part #: NOPOP
L3 L5 L24 L26 = INDUCTOR: Part #: 104949-1721R
L6 = INDUCTOR: Part #: 104948-1330R
L7 L18 = INDUCTOR: Part #: 104949-1181R
L12 L16 = INDUCTOR: Part #: 104948-1621R
L13 = INDUCTOR: Part #: 104947-0100R
L14 L15 = INDUCTOR: Part #: 104949-1100R
L17 L21 = INDUCTOR: Part #: 104949-1391R
L19 = INDUCTOR: Part #: 104947-0150R
L20 L22 = INDUCTOR: Part #: 104949-1160R
L23 L25 = INDUCTOR: Part #: 104949-1681R
L27 L31 = FERRITE_CHIP_0: Part #: 101735-1002R
PL1 = PL0201: Part #: NOPOP
R24 = R: Part #: 102145-1201R
R81 R82 R85-R92 = R_1: Part #: 103413-4420R
TP9 TP18 = TP-30RD13: Part #: TP-30RD13-NO-POP
TP21 TP22 TP24-TP31 = TP-20RD10: Part #: TP-20RD10-NO-POP
U19 = Si47972: Part #: 105335-0001R
U22 U23 = SN74LVC1G125_0: Part #: 101057-0125R
U25 = SN74AVC8T245_1: Part #: 102708-0001R
Y6 = CRYSTAL_4-PIN_0: Part #: 104897-3686R
C240 C260 C261 C273 C281 C286 = Cap_100nF_Cermc_16V_10%_603_4: Part #: 105047-1100R; Voltage: 6.3V
C259 = CAP: Part #: 105312-0101R; Voltage: 16V
C283 = CAP: Part #: C0603-NOPOP
C289 = CAP: Part #: 102963-0101R
P5 = molex-502774-0891: Part #: 105161-0001R
R112 = RESISTOR: Part #: 103158-1002R
R319 R322 R335 R340 R344 R347 R350 = RESISTOR: Part #: 103413-3600R
R320 R336 R339 R345 R346 R351 = RESISTOR: Part #: 103158-4703R
U36 = TPS22965DSGT_WSON8_0: IC 6A,16mOHM ON RESISTANCE LOAD SWITCH WSON8; Chkd/date: MANIRAJA/110817; Crtd /date: MANIRAJA/110817; Custom_Duty: 15%; Customs_HS_Code: 85423100; Distributor_name: DIGIKEY; Distributor_part_number: 296-42375-1-ND; Height: 0.80MM; Library Ref: TPS22965DSGT_WSON8; Mfr_name: TEXAS INSTRUMENTS; Mfr_part_number: TPS22965DSGT; Mistral Part No: 142017080006-R; Package: WSON8; Part #: 104267-0001R; Part_type: ICS\POWER\DRIVER; Project: TI_SVB_MAXWELL_DUT; RoHS: RoHS; Temperature: -40°C+105°C; Tolerance: NA; Voltage: NA; Wattage: NA; Weight: 11mg; Datasheet: Y:\MIS_DATABASE\DATASHEETS\ICS\POWER\TPS22965N.PDF
U69-U72 = TPDE0001RSE_0: Part #: 102728-0001R

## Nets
DGND: C30.2 C34.2 C38.2 C44.2 C49.2 C50.2 C51.2 C52.2 C55.1 C58.2 C59.2 C61.2 C69.2 C77.2 C79.2 C82.2 C87.2 C88.2 C89.2 C92.1 C97.2 C101.2 C107.2 C132.2 C133.2 C134.2 C240.2 C259.2 C260.2 C261.2 C273.2 C281.2 C283.2 C286.2 C289.2 C295.2 C296.2 C301.2 C303.2 C305.1 C307.2 C308.2 C321.2 C332.2 C345.2 C346.2 C348.2 C367.2 C368.2 C369.2 C370.2 C371.2 C372.2 C374.2 C375.2 C382.2 C387.2 C393.2 C406.2 C407.2 C408.2 C415.2 C416.2 C441.2 C449.2 C456.2 C506.2 C507.2 C508.2 C511.2 C512.2 C515.2 C516.2 C522.1 C523.2 C524.2 C526.2 C531.2 C532.2 C533.2 C534.2 C551.1 C561.1 C562.1 C566.1 C567.1 C746.2 C749.2 C750.2 C751.2 C765.2 C766.2 C768.2 C778.2 C779.2 C780.2 C781.2 C783.2 C784.2 C785.2 C786.2 C787.2 C788.2 C789.2 C790.2 C794.2 C795.2 C811.2 D2.2 D3.2 D5.2 J5.2 J5.3 J5.4 J5.5 J7.2 J7.3 J7.4 J7.5 J10.2 J13.5 J13.6 J13.11 J13.12 J15.16(Gnd16) J15.57(Gnd57) J15.58(Gnd58) J15.61(GndCt1) J15.62(GndCt2) J15.63(GndCt3) J15.64(GndCt4) J19.5(USBVSS) J20.4(GND) J20.9(GND) J20.15(GND) J20.18(GND) J20.21(GND) J20.26(GND) J20.27(GND) J20.29(GND) J20.34(GND) J20.35(GND) J20.37(GND) J20.40(GND) J20.43(GND) J20.50(GND) L6.1 L23.1 L24.1 L25.1 L26.1 M5.1 M6.1 P5.6(VSS) PL1.2 Q6.S R21.2 R32.2 R34.2 R35.1 R37.2 R60.1 R64.1 R112.2 R148.1 R214.2 R216.2 R218.2 R227.2 R231.2 R235.1 R255.1 R275.1 R276.1 R278.1 R279.1 R280.2 R368.2 R369.2 R377.2 R391.2 R394.1 R405.1 R413.1 R425.2 RJ18.3 SW3.1(A) SW3.2(AA) U10.3(GND) U16.49(GND(PAD)) U19.32(SMMODE) U19.33(NVMISO) U19.34(NVMOSI) U19.35(NVSSB) U19.36(NVSCLK) U19.56(DFS1) U19.57(DCLK1) U19.62(DIFS4) U19.63(DICLK4) U19.65(DIFS3) U19.66(DICLK3) U19.68(DIFS2) U19.69(DICLK2) U19.70(DIN2) U19.71(DIFS1) U19.72(DICLK1) U19.73(DIN1) U19.74(GP1) U19.75(GP2) U19.76(GP0) U19.77(DIN0) U19.78(DICLKA) U19.79(DIFSA) U19.80(DICLK0) U19.81(DIFSO) U19.83(ICP) U19.89(EPAD) U22.1(OE) U22.3(GND) U23.1(OE) U23.3(GND) U25.11(GND) U25.12(GND) U25.13(GND) U25.22(OEn) U25.25(PP) U36.5(GND) U36.9(EP) U39.5(GND) U39.7(PAD) U41.2(GND) U42.37(GND) U43.2(GND) U44.2(GND) U47.3(GND) U48.3(GND) U49.3(GND) U50.2(GND) U51.3(2DIR) U51.8(GND.1) U51.9(GND.2) U51.14(2~{OE}) U51.15(1~{OE}) U51.17(GND.3) U52.1(GND) U52.5(GND) U52.10(AGND) U52.11(GND) U52.13(TEST) U52.15(GND) U52.25(GND) U52.35(GND) U52.47(GND) U52.51(GND) U53.3(GND) U53.7(GND) U55.3(2DIR) U55.8(GND.1) U55.9(GND.2) U55.14(2~{OE}) U55.17(GND.3) U56.2(GND) U60.4(GND) U69.4(GND) U70.4(GND) U71.4(GND) U72.4(GND) Y3.2(GND1) Y3.4(GND2) Y5.2(NC1) Y5.4(NC2) Y6.2(GND1) Y6.4(GND2) ; also on sheet 8 9 10 11 12 13 14 15 17 18 19 20 21 22 23 24 25 26 27 28 29 30 31 32 33 39 40
VBAT_SYS: C787.1 RJ18.1 U50.10(VSUP) ; also on sheet 21 22 23
VCC_1V1USB: C82.1 C506.1 C508.1 C515.1 C516.1 C531.1 C533.1 FL4.1 RJ1.1 U16.1(VDD) U16.12(VDD) U16.18(VDD) U16.30(VDD) U16.34(VDD) U16.45(VDD)
VDD_1P0: C303.1 FL14.1 R152.2 R176.2
VDD_IO_3V3: C51.1 C55.2 C59.1 C87.1 C88.1 C116.1 C117.1 C118.1 C144.1 C146.1 C150.1 C281.1 C289.1 C295.1 C551.2 C561.2 C562.2 C566.2 C567.2 C789.1 FL5.2 FL13.2 FL16.1 J20.2(3.3VAUX) J20.24(+3.3VAUX) J20.39(+3.3VAUX) J20.41(+3.3VAUX) J20.52(+3.3VAUX) L27.1 R6.1 R29.1 R31.1 R36.2 R38.2 R41.1 R42.1 R68.2 R142.1 R273.2 R274.2 R393.1 U10.5(VCC) U19.42(VIO1) U19.45(VIO2) U22.5(VCC) U23.5(VCC) U25.1(VCCA) U25.2(DIR) U25.23(VCCB) U25.24(VCCB) U36.1(VIN1) U36.2(VIN2) U36.4(VBIAS) U39.3(EN) U39.4(BIAS) U39.6(IN) U51.16(VCCB) ; also on sheet 10 15 16 18 21 25 26 27 28 29 30 31 32 39 40
VDD_MCUIO_3V3: C781.1 C786.1 C794.1 R408.1 R410.1 R412.1 R414.1 R415.1 R424.1 U44.5(VIO/NC) U50.5(VIO) U55.16(VCCB) ; also on sheet 14 18 23 24 25 26 39
VDD_SD_DV: R320.1 R321.1 R336.1 R339.1 R345.1 R346.1 R351.1 ; also on sheet 18 24
VDDA_TC811: C301.1 C750.1 C751.1 C766.1 FL13.1 R154.1 R177.1 R178.1 R179.1 R357.2 U42.11(VDDA)
VDDIO_TC811: C345.1 C346.1 C779.1 C780.1 C783.1 C784.1 FL16.2 R165.2 R362.2 U42.22(VDDIO)
A72_CONSOLE_RXD: R212.2 ; also on sheet 15
A72_CONSOLE_TXD: R216.1 U51.11(2B1) ; also on sheet 15
AMI: C66.1 R27.1 U19.13(AMI)
B3A: C62.1 L23.2 U19.9(B3A)
CAN_POWER_ON_HV: R392.1 ; also on sheet 23
CAN_WAKE: J13.10 R220.1 R406.2 RJ18.2
CANH_1: J13.4 R409.1 U50.13(CANH)
CANH_2: J13.9 R387.1 U44.7(CANH)
CANL_1: J13.3 R404.2 U50.12(CANL)
CANL_2: J13.8 R384.2 U44.6(CANL)
CON_MMC1_CLK: P5.5(CLK) R340.2 U71.3(IO1)
CON_MMC1_CMD: P5.3(CMD) R344.2 U71.5(IO2)
CON_MMC1_DAT0: P5.7(DAT0) R335.2 U70.5(IO2)
CON_MMC1_DAT1: P5.8(DAT1) R322.2 U70.3(IO1)
CON_MMC1_DAT2: P5.1(DAT2) R350.2 U72.5(IO2)
CON_MMC1_DAT3: P5.2(DAT3) R347.2 U72.3(IO1)
D3B: C68.1 L25.2 U19.10(B3B)
DEBUGN: J10.3 U19.54(DEBUGN)
DEBUGP: J10.1 U19.55(DEBUGP)
DOUT0: U19.61(DOUT0) U23.2(I)
DOUT1: U19.58(DOUT1) U22.2(I)
EMU_RSTn: J15.6(nRESET) ; also on sheet 14
EN_3V3IO_LDSW: Q6.G ; also on sheet 21 24 25 40
ENET_EN: R364.1 ; also on sheet 10
ENET_INH: R369.1 U42.10(INH) ; also on sheet 13
ENET_INTSn: R362.1 R363.1 ; also on sheet 13
ENET_WAKE: R368.1 U42.8(WAKE) ; also on sheet 16
EXT_TDI: J15.5(TDI) U48.2(I)
EXT_TDO: J15.4(TDO) U47.4(O)
EXT_TMS: J15.2(TMS) U49.2(I)
FMA: C71.1 C79.1 L26.2 U19.8(FMA)
FMB: C67.1 C77.1 L24.2 U19.11(FMB)
G720_VDD1A: C307.1 R152.1 U42.9(NC9)
G720_VDD1B: C332.1 R176.1 U42.21(NC21)
G720_VDDIO: C768.1 R165.1 U42.34(TX_ER)
G720_VSLEEP: R357.1 R364.2 U42.7(EN)
H_MMC1_CLK: R336.2 R340.1 ; also on sheet 10
H_MMC1_CMD: R344.1 R346.2 ; also on sheet 10
H_MMC1_D0: R335.1 R339.2 ; also on sheet 10
H_MMC1_D1: R320.2 R322.1 ; also on sheet 10
H_MMC1_D2: R350.1 R351.2 ; also on sheet 10
H_MMC1_D3: R345.2 R347.1 ; also on sheet 10
H_MMC1_SDCD: R319.1 R321.2 ; also on sheet 10
I2C4_SCL: R30.2 ; also on sheet 16
I2C4_SDA: R28.2 ; also on sheet 16
ICN: R64.2 U19.82(ICN)
MCAN_EN: R390.1 ; also on sheet 14
MCAN_nFAULT: R407.1 ; also on sheet 14
MCU_CAN0_STBz: R403.1 ; also on sheet 14
MCU_CAN1_STBz: R386.1 ; also on sheet 14
MCU_CONSOLE_RXD: R223.2 ; also on sheet 14
MCU_CONSOLE_TXD: U55.11(2B1) ; also on sheet 14
MCU_MCAN0_RX: R389.1 ; also on sheet 14
MCU_MCAN0_TX: R388.1 ; also on sheet 14
MCU_MCAN1_RX: R372.1 ; also on sheet 14
MCU_MCAN1_TX: R371.1 ; also on sheet 14
MCUBOOT_BUFF_ENz: U55.15(1~{OE}) ; also on sheet 14 22 39
MDIO0_MDC: U42.1(MDC) ; also on sheet 13
MDIO0_MDIO: R154.2 U42.36(MDIO) ; also on sheet 13
MMC_PWR_ON: R142.2 U36.3(ON) ; also on sheet 16
nTRST: J15.9(nTRST) R412.2 RJ19.3
PCIe0_CLKREQ#: J20.7(CLKREQ#) R41.2 ; also on sheet 15
PCIe0_PERSTz: J20.22(PERST#) U10.4(Y)
PCIe0_RC_RSTz: R32.1 U10.1(A) ; also on sheet 16
PCIE0_REFCLK_N: J20.11(REFCLK-) ; also on sheet 9
PCIE0_REFCLK_P: J20.13(REFCLK+) ; also on sheet 9
PCIe0_RX0_N: J20.23(PERN0) ; also on sheet 9
PCIe0_RX0_P: J20.25(PERP0) ; also on sheet 9
PCIe0_SCL: J20.30(SMB_CLK) R30.1 R31.2
PCIe0_SDA: J20.32(SMB_DATA) R28.1 R29.2
PCIe0_TX0_N: J20.31(PETN0) ; also on sheet 9
PCIe0_TX0_P: J20.33(PETP0) ; also on sheet 9
PCIe0_USB_D+: FL2.3 U16.14(USB_DP_DN2)
PCIe0_USB_D-: FL2.2 U16.15(USB_DM_DN2)
PCIe0_W_DISABLE#: J20.20(W_DISABLE#) R21.1 ; also on sheet 16
PCIe0_WAKE#: J20.1(WAKE#) R42.2 ; also on sheet 16
RGMII5_RD0: R179.2 U42.26(RX_D0) ; also on sheet 13
RGMII5_RD1: R178.2 U42.25(RX_D1) ; also on sheet 13
RGMII5_RD2: R177.2 U42.24(RX_D2) ; also on sheet 13
RGMII5_RD3: U42.23(RX_D3) ; also on sheet 13
RGMII5_RX_CTL: U42.15(RX_DV/CRS_DIV/RX_CTRL) ; also on sheet 13
RGMII5_RXC: U42.27(RX_CLK) ; also on sheet 13
RGMII5_TD0: U42.33(TX_D0) ; also on sheet 13
RGMII5_TD1: U42.32(TX_D1) ; also on sheet 13
RGMII5_TD2: U42.31(TX_D2) ; also on sheet 13
RGMII5_TD3: U42.30(TX_D3) ; also on sheet 13
RGMII5_TX_CTL: U42.29(TX_EN/TX_CTRL) ; also on sheet 13
RGMII5_TXC: U42.28(TX_CLK) ; also on sheet 13
SOC_EMU0: J15.19(TRD0.1) R414.2 ; also on sheet 14
SOC_EMU1: J15.21(TRD0.2) R415.2 ; also on sheet 14
SOC_PORZ_OUT: U10.2(B) U16.11(GRSTZ) U42.3(RESET_N) ; also on sheet 14 27
SOC_TCK: J15.3(TCK) R410.2 R411.2 ; also on sheet 14
SOC_TDI: U48.4(O) ; also on sheet 14
SOC_TDO: U47.2(I) ; also on sheet 14
SOC_TMS: R393.2 U49.4(O) ; also on sheet 14
SOC_TRST#: RJ19.2 ; also on sheet 14
TRD1_N: C316.1 J13.2 R170.1
TRD1_P: C312.1 J13.1 R161.1
TRD_N: C319.1 L42.1 U42.13(TRD_N)
TRD_P: C311.1 L40.1 U42.12(TRD_P)
TRSTPD: J15.8(TRSTPD) R425.1 RJ19.1
TUNER0_IQ_ACLKR: R89.2 TP30.1(TP) ; also on sheet 16
TUNER0_IQ_AXR0: R90.2 TP26.1(TP) ; also on sheet 16
TUNER0_IQ_AXR1: R88.2 TP25.1(TP) ; also on sheet 16
TUNER0_IQ_FSR: R87.2 TP29.1(TP) ; also on sheet 16
TUNER1_IQ_ACLKR: R91.2 TP31.1(TP) ; also on sheet 16
TUNER1_IQ_AXR0: R86.2 TP24.1(TP) ; also on sheet 16
TUNER1_IQ_AXR1: R85.2 TP28.1(TP) ; also on sheet 16
TUNER1_IQ_FSR: R92.2 TP27.1(TP) ; also on sheet 16
TUNER_AGND: PL1.1 ; also on sheet 32
TUNER_AUDIO_ACLKX: TP22.1(TP) U19.60(DCLK0) ; also on sheet 16
TUNER_AUDIO_AXR0: U19.67(DIN3) ; also on sheet 16
TUNER_AUDIO_AXR1: U19.64(DIN4) ; also on sheet 16
TUNER_AUDIO_AXR10: R82.2 ; also on sheet 16
TUNER_AUDIO_AXR11: R81.2 ; also on sheet 16
TUNER_AUDIO_FSX: TP21.1(TP) U19.59(DFSO) ; also on sheet 16
TUNER_IN1M: U19.20(AIN0N) ; also on sheet 33
TUNER_IN1P: U19.19(AIN0P) ; also on sheet 33
TUNER_IN2M: U19.22(AIN1N) ; also on sheet 33
TUNER_IN2P: U19.21(AIN1P) ; also on sheet 33
TUNER_IN3M: U19.24(AIN2N) ; also on sheet 33
TUNER_IN3P: U19.23(AIN2P) ; also on sheet 33
TUNER_IN4M: U19.26(AIN3N) ; also on sheet 33
TUNER_IN4P: U19.25(AIN3P) ; also on sheet 33
TUNER_IN5M: U19.28(AIN4N) ; also on sheet 33
TUNER_IN5P: U19.27(AIN4P) ; also on sheet 33
TUNER_IN6M: U19.30(AIN5N) ; also on sheet 33
TUNER_IN6P: U19.29(AIN5P) ; also on sheet 33
TUNER_INTB_CHIP0: R68.1 U19.37(INTB) ; also on sheet 13
TUNER_OUT0: U19.84(AOUT0) ; also on sheet 32
TUNER_OUT1: U19.85(AOUT1) ; also on sheet 32
TUNER_OUT2: U19.86(AOUT2) ; also on sheet 32
TUNER_OUT3: U19.87(AOUT3) ; also on sheet 32
TUNER_RSTB_CHIP0: R280.1 U19.31(RSTB) ; also on sheet 13
TUNER_SPI_CS0: U19.41(SSB/A1) ; also on sheet 16
TUNER_SPI_D0: U19.39(MOSI/SDA) ; also on sheet 16
TUNER_SPI_D1: U19.38(MISO/A0) ; also on sheet 16
TUNER_SPI_SCLK: U19.40(SCLK/SCL) ; also on sheet 16
USART_A_RXD: R226.1 U52.17(ADBUS1/RXD/TDI)
USART_A_TXD: U52.16(ADBUS0/TXD/TCK) U55.4(1A1)
USART_B_RXD: R217.1 U52.39(BDBUS1/RXD/TDI)
USART_B_TXD: U51.4(1A1) U52.38(BDBUS0/TXD/TCK)
USART_DM: J19.2(D-) U52.7(USBDM) U60.5(IO2)
USART_DP: J19.3(D+) U52.8(USBDP) U60.3(IO1)
USART_EECS: R238.1 U52.63(EECS) U56.5(CS)
USART_EEDIN: R232.2 U52.61(EEDATA) U56.3(DIN)
USART_EEDOUT: R232.1 R239.1 U56.1(DO)
USART_EESK: R432.1 U52.62(EESK) U56.4(CLK)
USART_GND: J19.6(SHIELD1) J19.7(SHIELD2) J19.8(SHIELD3) J19.9(SHIELD4) R255.2
USART_LED: D14.2(ANODE) R237.2
USART_NR: C374.1 U53.2(NR)
USART_OSCI: C441.1 U52.2(OSCI) Y5.1
USART_OSCO: C449.1 U52.3(OSCO) Y5.3
USART_PD: R227.1 U51.5(1A2) U51.10(2B2) U55.5(1A2) U55.10(2B2)
USART_PWREN: D14.1(cathode) U52.60(PWREN#)
USART_RESETn: R236.2 U52.14(RESET#)
USART_RSET: R235.2 U52.6(REF)
USB1_DATA_N: U16.27(USB_DM_UP) ; also on sheet 15
USB1_DATA_P: U16.26(USB_DP_UP) ; also on sheet 15
USB1_DRVVBUS: RJ1.3 ; also on sheet 15
USB1_HUB_D_N: U16.42(USB_DM_DN1) ; also on sheet 28
USB1_HUB_D_P: U16.41(USB_DP_DN1) ; also on sheet 28
USB1_HUB_PWRCLT1: U16.4(PWRCLT1/BATEN1) ; also on sheet 28
VIO_3V3_SD: C259.1 C260.1 C261.1 C273.1 C286.1 P5.4(VDD) U36.7(VOUT1) U36.8(VOUT2) U70.1(VCC) U71.1(VCC) U72.1(VCC)
VIO_3V3USB: C97.1 C507.1 C511.1 C512.1 C523.1 C524.1 C526.1 C532.1 C534.1 FL5.1 U16.7(VDD33) U16.13(VDD33) U16.23(VDD33) U16.25(VDD33) U16.33(VDD33) U16.37(VDD33) U16.40(VDD33) U16.48(VDD33)
VPCIE0_1V5: C52.1 C58.1 J20.6(1.5V) J20.28(+1.5V) J20.48(+1.5V) ; also on sheet 40
VPHY_USART: C408.1 C415.1 L47.1 U52.4(VPHY)
VPLL_USART: C406.1 C416.1 L48.1 U52.9(VPLL)
VSYS_3V3: C348.1 R191.1 U47.5(VCC) U48.5(VCC) U49.5(VCC) ; also on sheet 17 22 23 25 40
VSYS_5V0: C765.1 C785.1 U44.3(VCC) U50.3(VCC) ; also on sheet 22 39 40
VSYS_IO_1V8: C132.1 C133.1 L31.1 ; also on sheet 30 31 39 40
VTUN_1V8: C125.1 C126.1 C127.1 C134.1 L31.2 TP18.1(TP) U19.43(VD)
VTUN_3V3: C83.2 C84.2 C85.2 C86.2 C89.1 C91.2 C93.2 L27.2 TP9.1(TP) U19.3(VA1) U19.18(VA2)
VUSART_1V8: C368.1 C369.1 C387.1 C407.1 U52.12(VCORE) U52.37(VCORE) U52.49(VREGOUT) U52.64(VCORE)
VUSART_3V3: C367.1 C370.1 C371.1 C372.1 C375.1 C382.1 C790.1 C795.1 C811.1 L47.2 L48.2 R236.1 R238.2 R239.2 R432.2 U51.1(VCCA) U51.2(1DIR) U52.20(VCCIO) U52.31(VCCIO) U52.42(VCCIO) U52.50(VREGIN) U52.56(VCCIO) U53.1(VOUT) U55.1(VCCA) U55.2(1DIR) U56.6(VCC)
VUSART_VBUS: C393.1 C456.1 J19.1(USBVDD) R237.1 U53.4(EN) U53.6(VIN) U60.1(VCC)
VUSB_IO_1V1: FL4.2 ; also on sheet 40
XTAL1: U19.6(XTALI) Y6.1(Y1)
XTAL2: U19.5(XTALO) Y6.3(C1)
ZIFCLK0: U19.50(ZIFCLK) U25.6(A4)
ZIFCLK1: U19.52(ISFSN) U25.4(A2)
ZIFFS0: U19.48(ZIFFS) U25.8(A6)
ZIFFS1: U19.53(ISFSP) U25.3(A1)
ZIFI0: U19.51(ZIFI0) U25.5(A3)
ZIFI1: U19.47(ZIFI1) U25.9(A7)
ZIFQ0: U19.49(ZIFQ0) U25.7(A5)
ZIFQ1: U19.46(ZIFQ1) U25.10(A8)
N29142214: C778.1 R384.1 R387.2
N29142221: R371.2 U44.1(TXD)
N29142246: R372.2 U44.4(RXD)
N29142266: R377.1 R386.2 U44.8(STB)
N29180491: J15.1(VREF_DBG) J15.12(VREF_TR) R424.2
N29180693: Q6.D R191.2 U47.1(OE) U48.1(OE) U49.1(OE)
N29180734: J15.7(RTCK) R411.1
N29180779: J15.15(TGT_DETECT) R413.2
N29182955: R223.1 U55.13(1B1)
N29183037: R226.2 R231.1 U55.6(2A1)
N29184661: R212.1 R214.1 U51.13(1B1)
N29185762: R217.2 R218.1 U51.6(2A1)
N29203019: C16.1 C25.2 D3.1 L5.1
N29203023: C25.1 C32.2 L12.2
N29203029: C32.1 C62.2 L17.2
N29203179: C34.1 L12.1
N29203181: C61.1 L17.1
N29203576: C16.2 J7.1
N29203584: R82.1 U23.4(O)
N29203608: R81.1 U22.4(O)
N29203733: C29.2 L5.2
N29203735: C29.1 L14.2 L18.2 L22.1
N29203745: C71.2 L22.2
N29203827: C522.2 U19.14(AMVAG)
N29203843: C38.1 L14.1
N29203845: C50.1 L18.1
N29203849: C83.1 C85.1 C91.1 U19.17(ABYP2)
N29203873: C116.2 C117.2 C118.2 C125.2 C126.2 C127.2 C144.2 C146.2 C150.2 U19.44(DBYP)
N29204635: C15.1 C22.1 C31.2 D2.1 L3.1
N29204639: C31.1 C48.2 L16.2
N29204645: C48.1 C68.2 L21.2
N29204746: C49.1 L16.1
N29204748: C69.1 L21.1
N29205057: C15.2 J5.1
N29205223: C27.2 L3.2
N29205225: C27.1 L7.2 L15.2 L20.1
N29205235: C67.2 L20.2
N29205377: C44.1 L15.1
N29205379: C30.1 L7.1
N29205614: C26.1 C40.1 C57.2 D5.1 L13.2 L19.1 R24.2
N29205618: C57.1 C66.2 L19.2 R24.1 R27.2
N29205650: C22.2 C26.2 L13.1
N29205730: C40.2 L6.2
N29457313: R274.1 TP10.1(TP) U16.2(SCL/SMBCLK)
N29457315: R273.1 TP11.1(TP) U16.3(SDA/SMBDAT)
N29457363: R35.2 RJ1.2 U16.9(USB_VBUS)
N29457411: R34.1 U16.10(TEST)
N29457441: R60.2 U16.24(USB_R1)
N29457479: R278.2 U16.35(GANGED/SMBA2)
N29457500: R279.2 U16.36(FULLPWWRMGMTTZ/SMBA1)
N29457524: R276.2 U16.22(SMBUSZ)
N29457542: R38.1 U16.5(OVERCUR1z)
N29457548: R275.2 U16.21(PWRCTL_POL)
N29457593: C107.1 R59.2 U16.38(XI) Y7.1
N29457640: R37.1 U16.6(PWRCTL2/BATEN2)
N29457654: C101.1 R59.1 U16.39(XO) Y7.2
N29457660: R36.1 U16.8(OVERCUR2z)
N29483068: FL2.4 J20.38(USB_D+)
N29483119: FL2.1 J20.36(USB_D-)
N29649764: D1.1(cathode) J20.44(LED_WLAN#)
N29668820: C296.1 FL14.2 U39.1(OUT)
N29890935: C92.2 U19.7(DACREF)
N29891501: C84.1 C86.1 C93.1 U19.2(ABYP1)
N30029908: R92.1 U25.21(B1)
N30029911: R91.1 U25.20(B2)
N30029914: R90.1 U25.19(B3)
N30029917: R88.1 U25.17(B5)
N30029920: R89.1 U25.18(B4)
N30029923: R87.1 U25.16(B6)
N30029926: R86.1 U25.15(B7)
N30029929: R85.1 U25.14(B8)
N31251157: C319.2 C321.1 R171.2
N31251611: L41.3 L42.2 R171.1 U43.1(IO)
N31252401: L40.2 L41.4 R162.1 U41.1(IO)
N31252434: C308.1 C311.2 R162.2
N31279750: R220.2 SW3.3(B) SW3.4(BB)
N32008315: D1.2(ANODE) R6.2
N32594642: P5.9(INSERT) R319.2 U69.5(IO2)
N32594704: P5.10(INSERT_COM) R112.1
N32594856: C240.1 U69.1(VCC)
N32595187: C283.1 U36.6(CT)
N33657189: C305.2 R148.2 R161.2 R170.2
N33657272: C312.2 L41.1
N33657370: C316.2 L41.2
N33657483: C746.1 U42.5(XI) Y3.3(C1)
N33657512: C749.1 U42.4(XO) Y3.1(Y1)
N33657557: R363.2 U42.2(INT_N)
N33657559: TP56.1(TP) U42.16(CLK_OUT/GPIO_2)
N33658409: R391.1 R392.2 U50.7(INH)
N33658469: R407.2 R408.2 U50.8(nFAULT)
N33658487: R390.2 R394.2 U50.6(EN)
N33658532: R403.2 R405.2 U50.14(nSTB)
N33658660: R406.1 U50.9(WAKE)
N33658666: C788.1 R404.1 R409.2
N33658711: R389.2 U50.4(RXD)
N33658728: R388.2 U50.1(TXD)

Not connected (* = marked no-connect by the designer): J13 7 13 14; J15 10(EXTE)* 11(EXTF)* 13(TR_CLK0)* 14(TR_CLK1)* 17(TRD0.0)* 18(TRD1.0)* 20(TRD1.1)* 22(TRD1.2)* 23(TRD0.3)* 24(TRD1.3)* 25(TRD0.4)* 26(TRD1.4)* 27(TRD0.5)* 28(TRD1.5)* 29(TRD0.6)* 30(TRD1.6)* 31(TRD0.7)* 32(TRD1.7)* 33(TRD0.8)* 34(TRD1.8)* 35(TRD0.9)* 36(TRD1.9)* 37(TRD3.0)* 38(TRD2.0)* 39(TRD3.1)* 40(TRD2.1)* 41(TRD3.2)* 42(TRD2.2)* 43(TRD3.3)* 44(TRD2.3)* 45(TRD3.4)* 46(TRD2.4)* 47(TRD3.5)* 48(TRD2.5)* 49(TRD3.6)* 50(TRD2.6)* 51(TRD3.7)* 52(TRD2.7)* 53(TRD3.8)* 54(TRD2.8)* 55(TRD3.9)* 56(TRD2.9)* 59(TR_CLK3)* 60(TR_CLK2)*; J19 4(ID)*; J20 3(COEX1) 5(COEX2) 8(UIM_PWR) 10(UIM_DATA) 12(UIM_CLK) 14(UIM_RESET) 16(UIM_VPP) 17(RSV/(UIM_C8)) 19(RSV/UIM_C4) 42(LED_WWAN#) 45(RSV45) 46(LED_WPAN#) 47(RSV47) 49(RSV49) 51(RSV51); P5 11 12 13 14; U16 16(RSVD16)* 17(RSVD17)* 19(RSVD10)* 20(RSVD20)* 28(RSVD28)* 29(RSVD29)* 31(RSVD31)* 32(RSVD32)* 43(RSVD43)* 44(RSVD44)* 46(RSVD46)* 47(RSVD47)*; U19 1(AOUT5)* 4(CLKO)* 12(AMO)* 15(LTB)* 16(LTA)* 88(AOUT4)*; U39 2(NC)*; U42 6(LED_1/GPIO_1)* 14(RX_ER)* 17(TCK)* 18(TDO)* 19(TMS)* 20(TDI)* 35(LED_0/GPIO_0)*; U50 11(NC); U51 7(2A2)* 12(1B2)*; U52 18(ADBUS2/RTS#/TDO) 19(ADBUS3/CTS#/TMS) 21(ADBUS4/DTR#/GPIOL0) 22(ADBUS5/DSR#/GPIOL1) 23(ADBUS6/DCD#/GPIOL2) 24(ADBUS7/RI#/GPIOL3) 26(ACBUS0/TXDEN/GPIOH0) 27(ACBUS1/WRSTB#/GPIOH1) 28(ACBUS2/RDSTB#/GPIOH2) 29(ACBUS3/RXLED#/GPIOH3) 30(ACBUS4/TXLED#/GPIOH4) 32(ACBUS5/-/GPIOH5) 33(ACBUS6/-/GPIOH6) 34(ACBUS7/-/GPIOH7) 36(SUSPEND#) 40(BDBUS2/RTS#/TDO) 41(BDBUS3/CTS#/TMS) 43(BDBUS4/DTR#/GPIOL0) 44(BDBUS5/DSR#/GPIOL1) 45(BDBUS6/DCD#/GPIOL2) 46(BDBUS7/RI#/GPIOL3) 48(BCBUS0/TXDEN/GPIOH0) 52(BCBUS1/WRSTB#/GPIOH1) 53(BCBUS2/RDSTB#/GPIOH2) 54(BCBUS3/RXLED#/GPIOH3) 55(BCBUS4/TXLED#/GPIOH4) 57(BCBUS5/-/GPIOH5) 58(BCBUS6/-/GPIOH6) 59(BCBUS7/-/GPIOH7); U53 5(NC); U55 7(2A2)* 12(1B2)*; U60 2(NC)*; U69 2(NC.2) 3(IO1); U70 2(NC.2); U71 2(NC.2); U72 2(NC.2)

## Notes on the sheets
sheet 34
- DEBUG CONSOLE
- Silkscreen: FTDI_VBUS
- Note:  Buffers used for voltage translation
  and signal isolation.
- Terminal
  Connector
- DO RX/TX SWAP
- TXDA
- Silkscreen: TERMINAL
- RXDA
- MCU_BOOTMODE[9:8],
  HIGH-Z UNTIL BOOT
  DONE.
- TXDB
- RXDB
- DEBUG JTAG
- TCK,TRSTn,EMU0,EMU1 ON VDDSHV0_MCU POWER DOMAIN.
  TMS,TDI,TDO ON VDDSHV0 POWER DOMAIN.
  ISOLATE TMS,TDI,TDO TO PREVENT EMULATOR
  DRIVING INTO SOC WHEN VDDSHV0 IS OFF.
  TCK,TRSTn,EMU0/1 DRIVE CONTROLLED BY
  VDDSHV0_MCU (I.E. VREF_DBG).
- XDS560v2(default jtag support)
- XDS560V2 OPEN-DRAIN,
  PULLUP AT
  DESTINATION TO
  APPROPRIATE VOLTAGE
  LEVEL IF USED.
- TRSTn ==  MIPI TRSTPD PULL DOWN VERSION
  TRSTn ==  MIPI nTRST MIPI PULLUP VERSION
  FOR CJTAG SET THE RJ TO PINS 3-2.
- DOUBLE CHECK VOLTAGE LEVEL ON EN_3V3IO_LDSW AND PULLDOWN.
sheet 35
- RADIO TUNER
- BAND3/FM
- TUNER_AGND IS DGND SIGNAL TRACE ROUTED WITH
  TUNER_OUTx TO TPA6304 IN_REF.
- BLACK
- ANTENNA FROM LCARD
- BAND3/FM/AM
- WHITE
- POWER FROM LCARD
- 0805,1K OHMS,1.5A
- 0805,1K OHMS,1.5A
sheet 36
- OPTIONAL SD CARD SUPPORT
- PLACE 36 OHM R NEAR TPD DEVICES
- ~97 micro second ramp
sheet 37
- ENET - DP83TC811/DP83TG720 (OPTION)
- Mating Connector Molex 0348241124
- DEBUG SUPPORT
- CAN WITH WAKEUP
- CAN_POWER_ON_HV HIGH == VBAT_SYS
  STATES ARE HIGH AND Z, SO PULL DOWN.
sheet 38
- USB HUB FOR WIFI/DEBUG
- USB HUB INCLUDED TO
  SUPPORT USB DEBUG PORT
  AND WIFI.
- USB_VBUS on HUB pin 9 must be high for the HUB to show
  up on the USB bus as this simulates up-stream power.
  However a high on USB_VBUS does NOT turn on down-stream
  power via PWRCTL.  PWRCTL to downstream ports is
  controlled via the USB power control SW stack.  Each
  down-stream power port is controlled individually.
  RJ16 - Option 1-2, 0-ohm,  HUB always active
  RJ16 - Option 2-3, 20K ohm, HUB active only when
  USB1_DRV_VBUS is high
- VIN MAX - 1.15V
- USB-DIFF-PAIR-90-OHM
- USB-DIFF-PAIR-90-OHM
- IPU
- IPU
- IPU
- IPD
- PWRCLT - NO BATTERY CHARGE, ACTIVE HIGH ON
  TO MATCH H_USB1_DRV_VBUS OPERATON.
- USB-DIFF-PAIR-90-OHM
- Mini PCIe Half Card Interface (WiFi Only)
- SX-PCEAC2-HMC-SP DOES NOT
  USE 1.5V OR I2C.
- 100E
- 100E
- 100E
- M2 MINI PCIE
  THREADED
  STANDOFF
